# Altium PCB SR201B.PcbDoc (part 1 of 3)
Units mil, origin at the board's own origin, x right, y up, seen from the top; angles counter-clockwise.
Board outline 4100 x 3600 mil, 4 copper layers (Top Layer, Signal Layer 1, Signal Layer 2, Bottom Layer), stack 61.6 mil thick; 173 components, 61 nets, 385 pads, 260 vias.
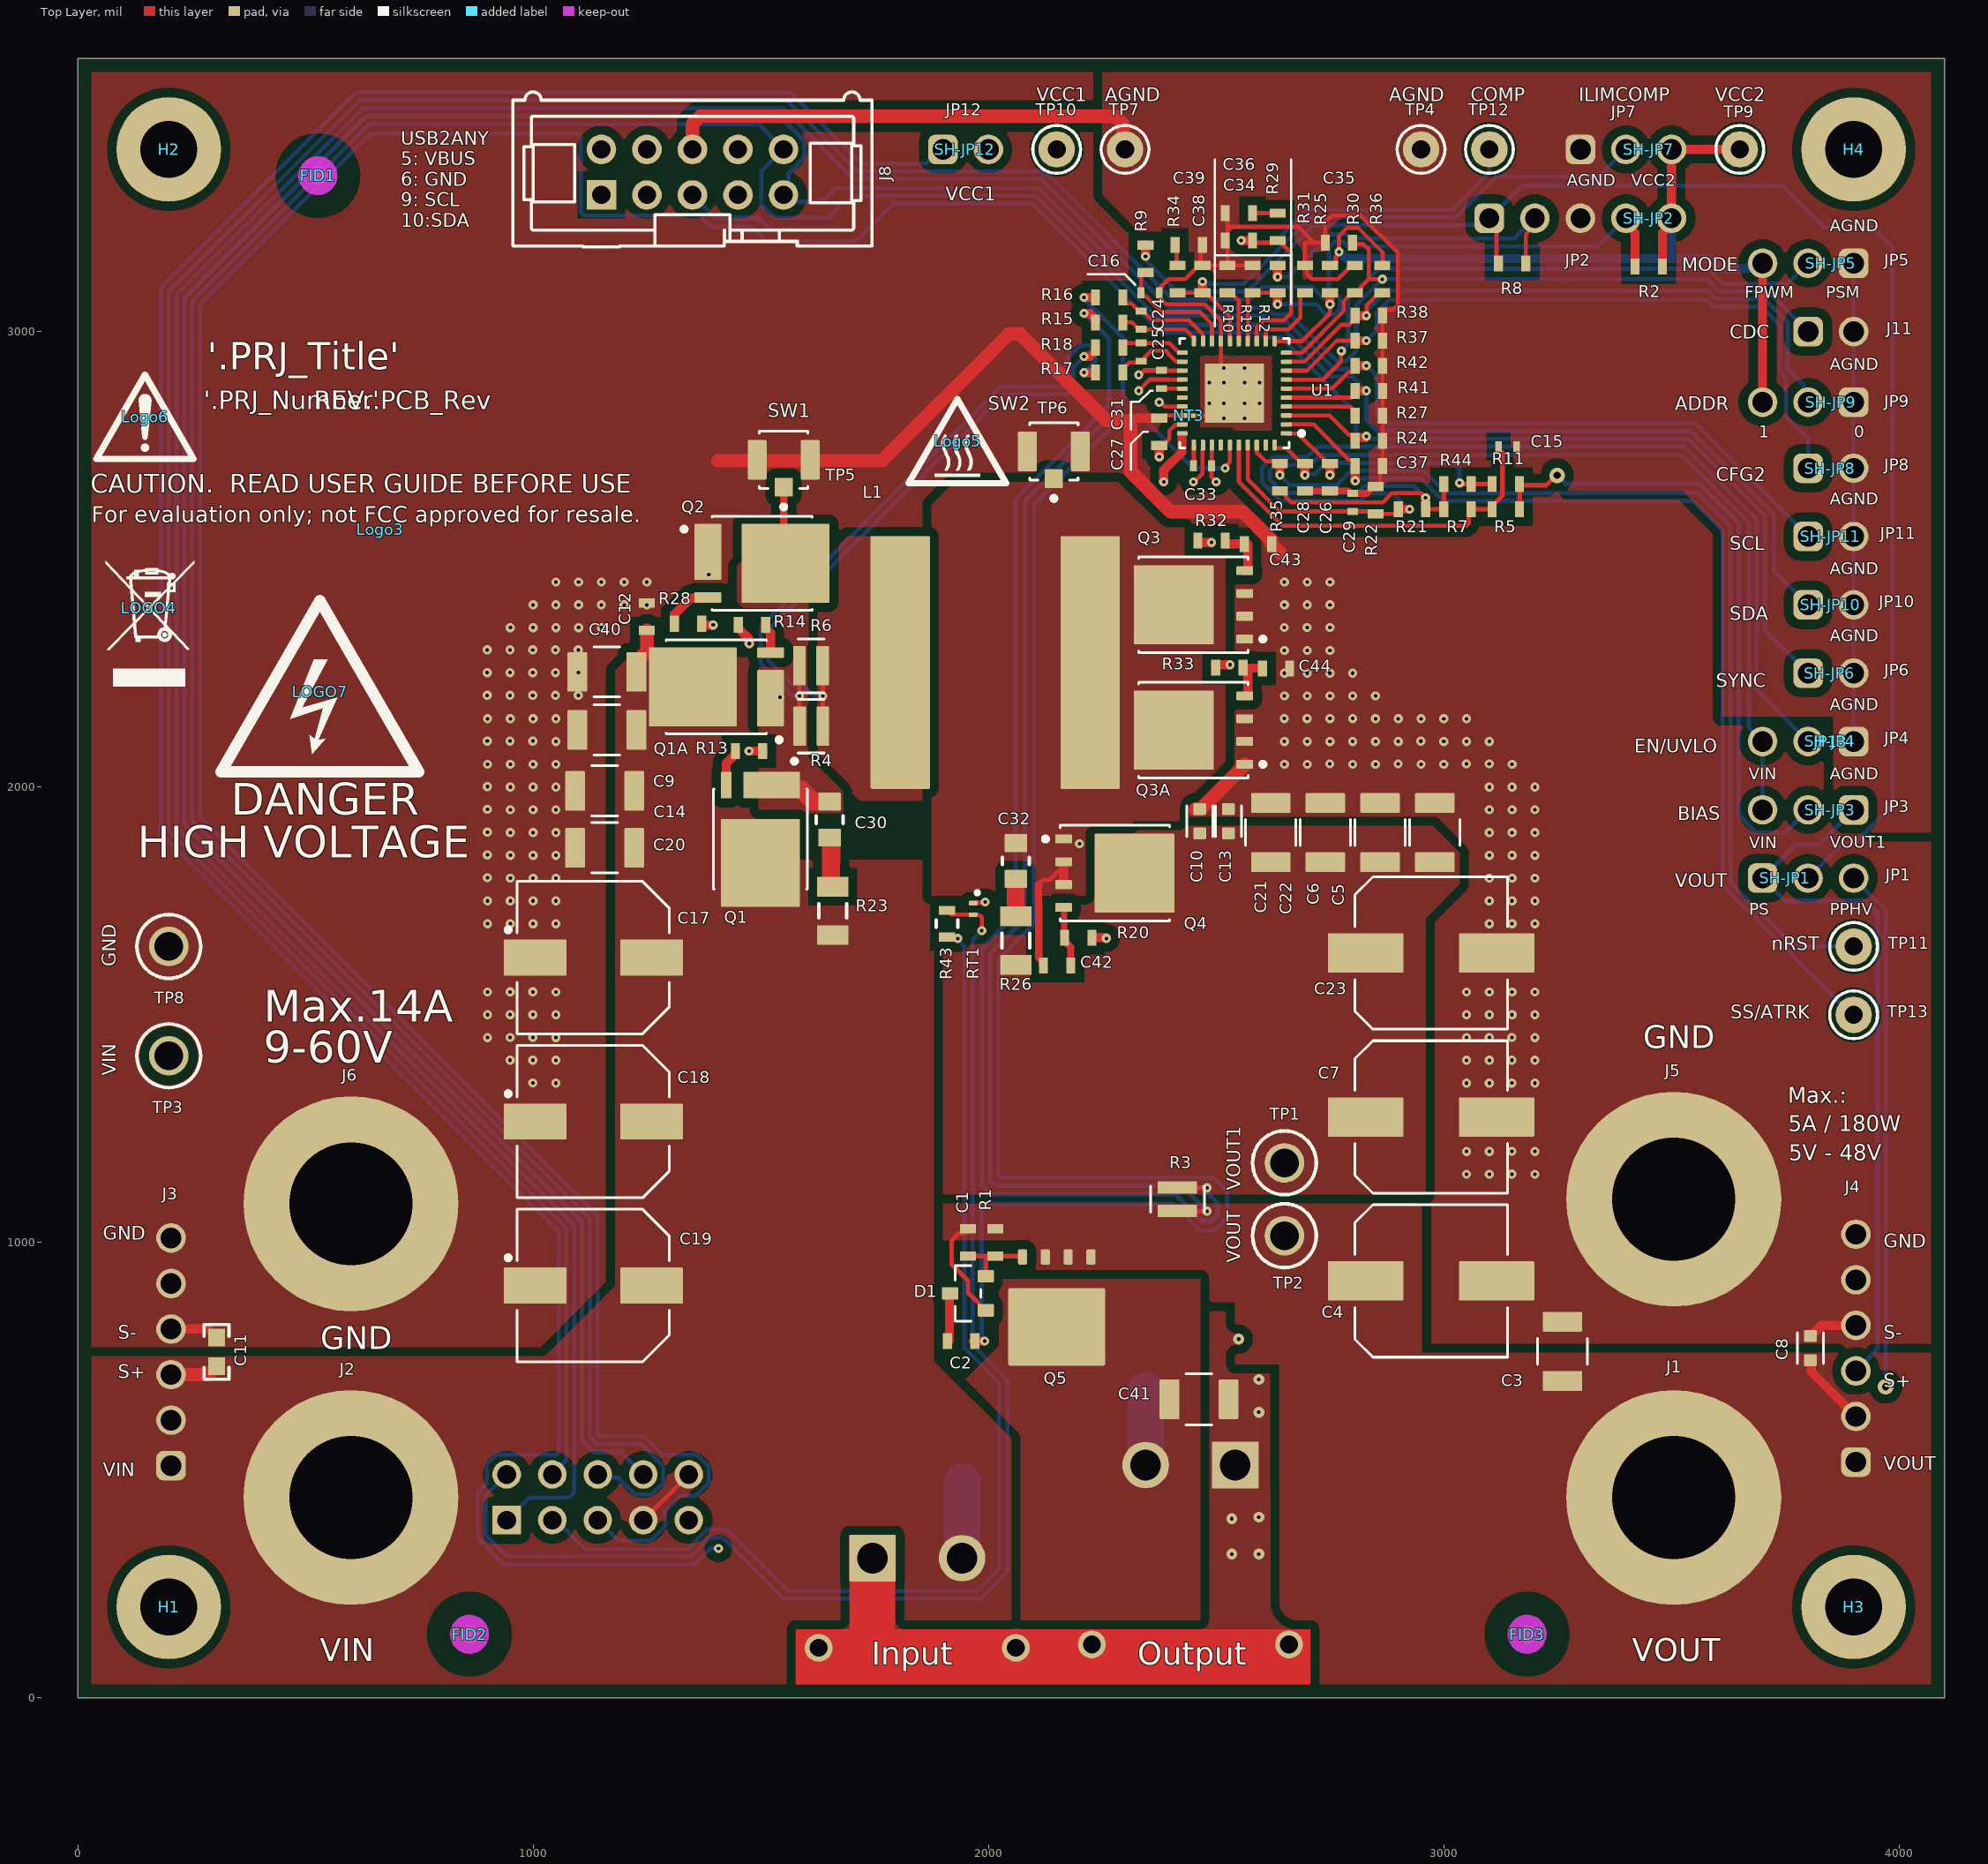
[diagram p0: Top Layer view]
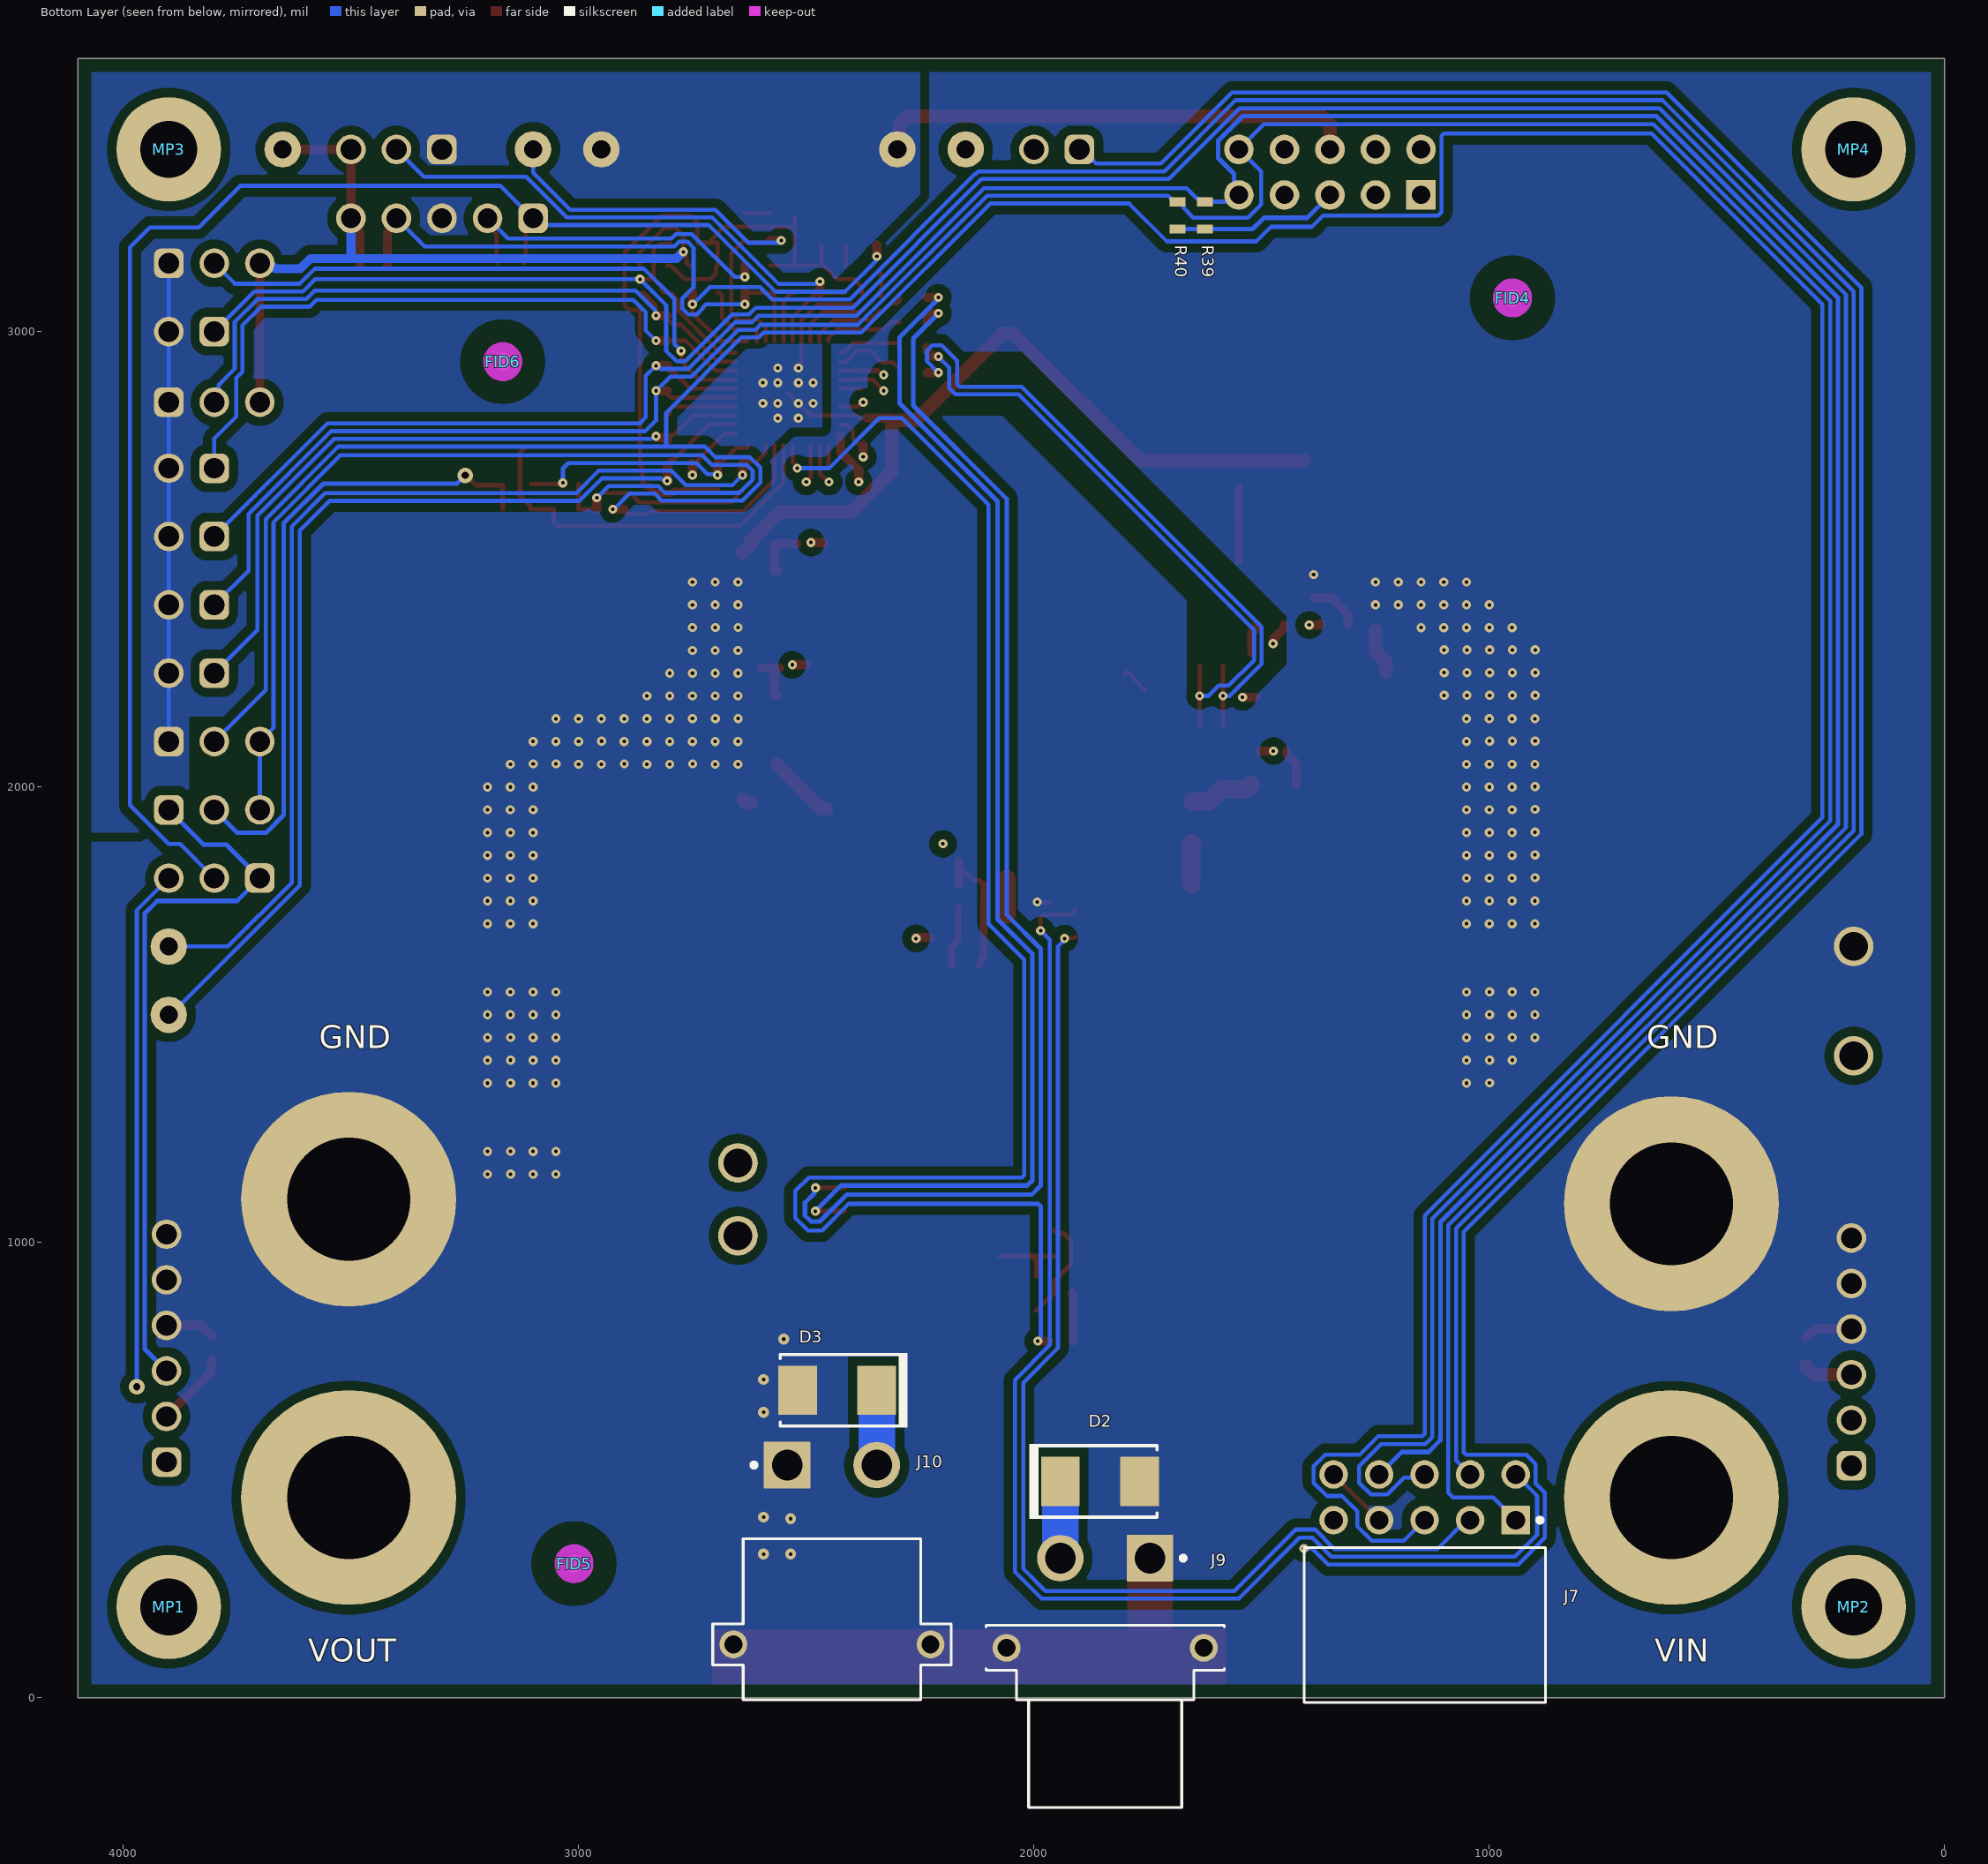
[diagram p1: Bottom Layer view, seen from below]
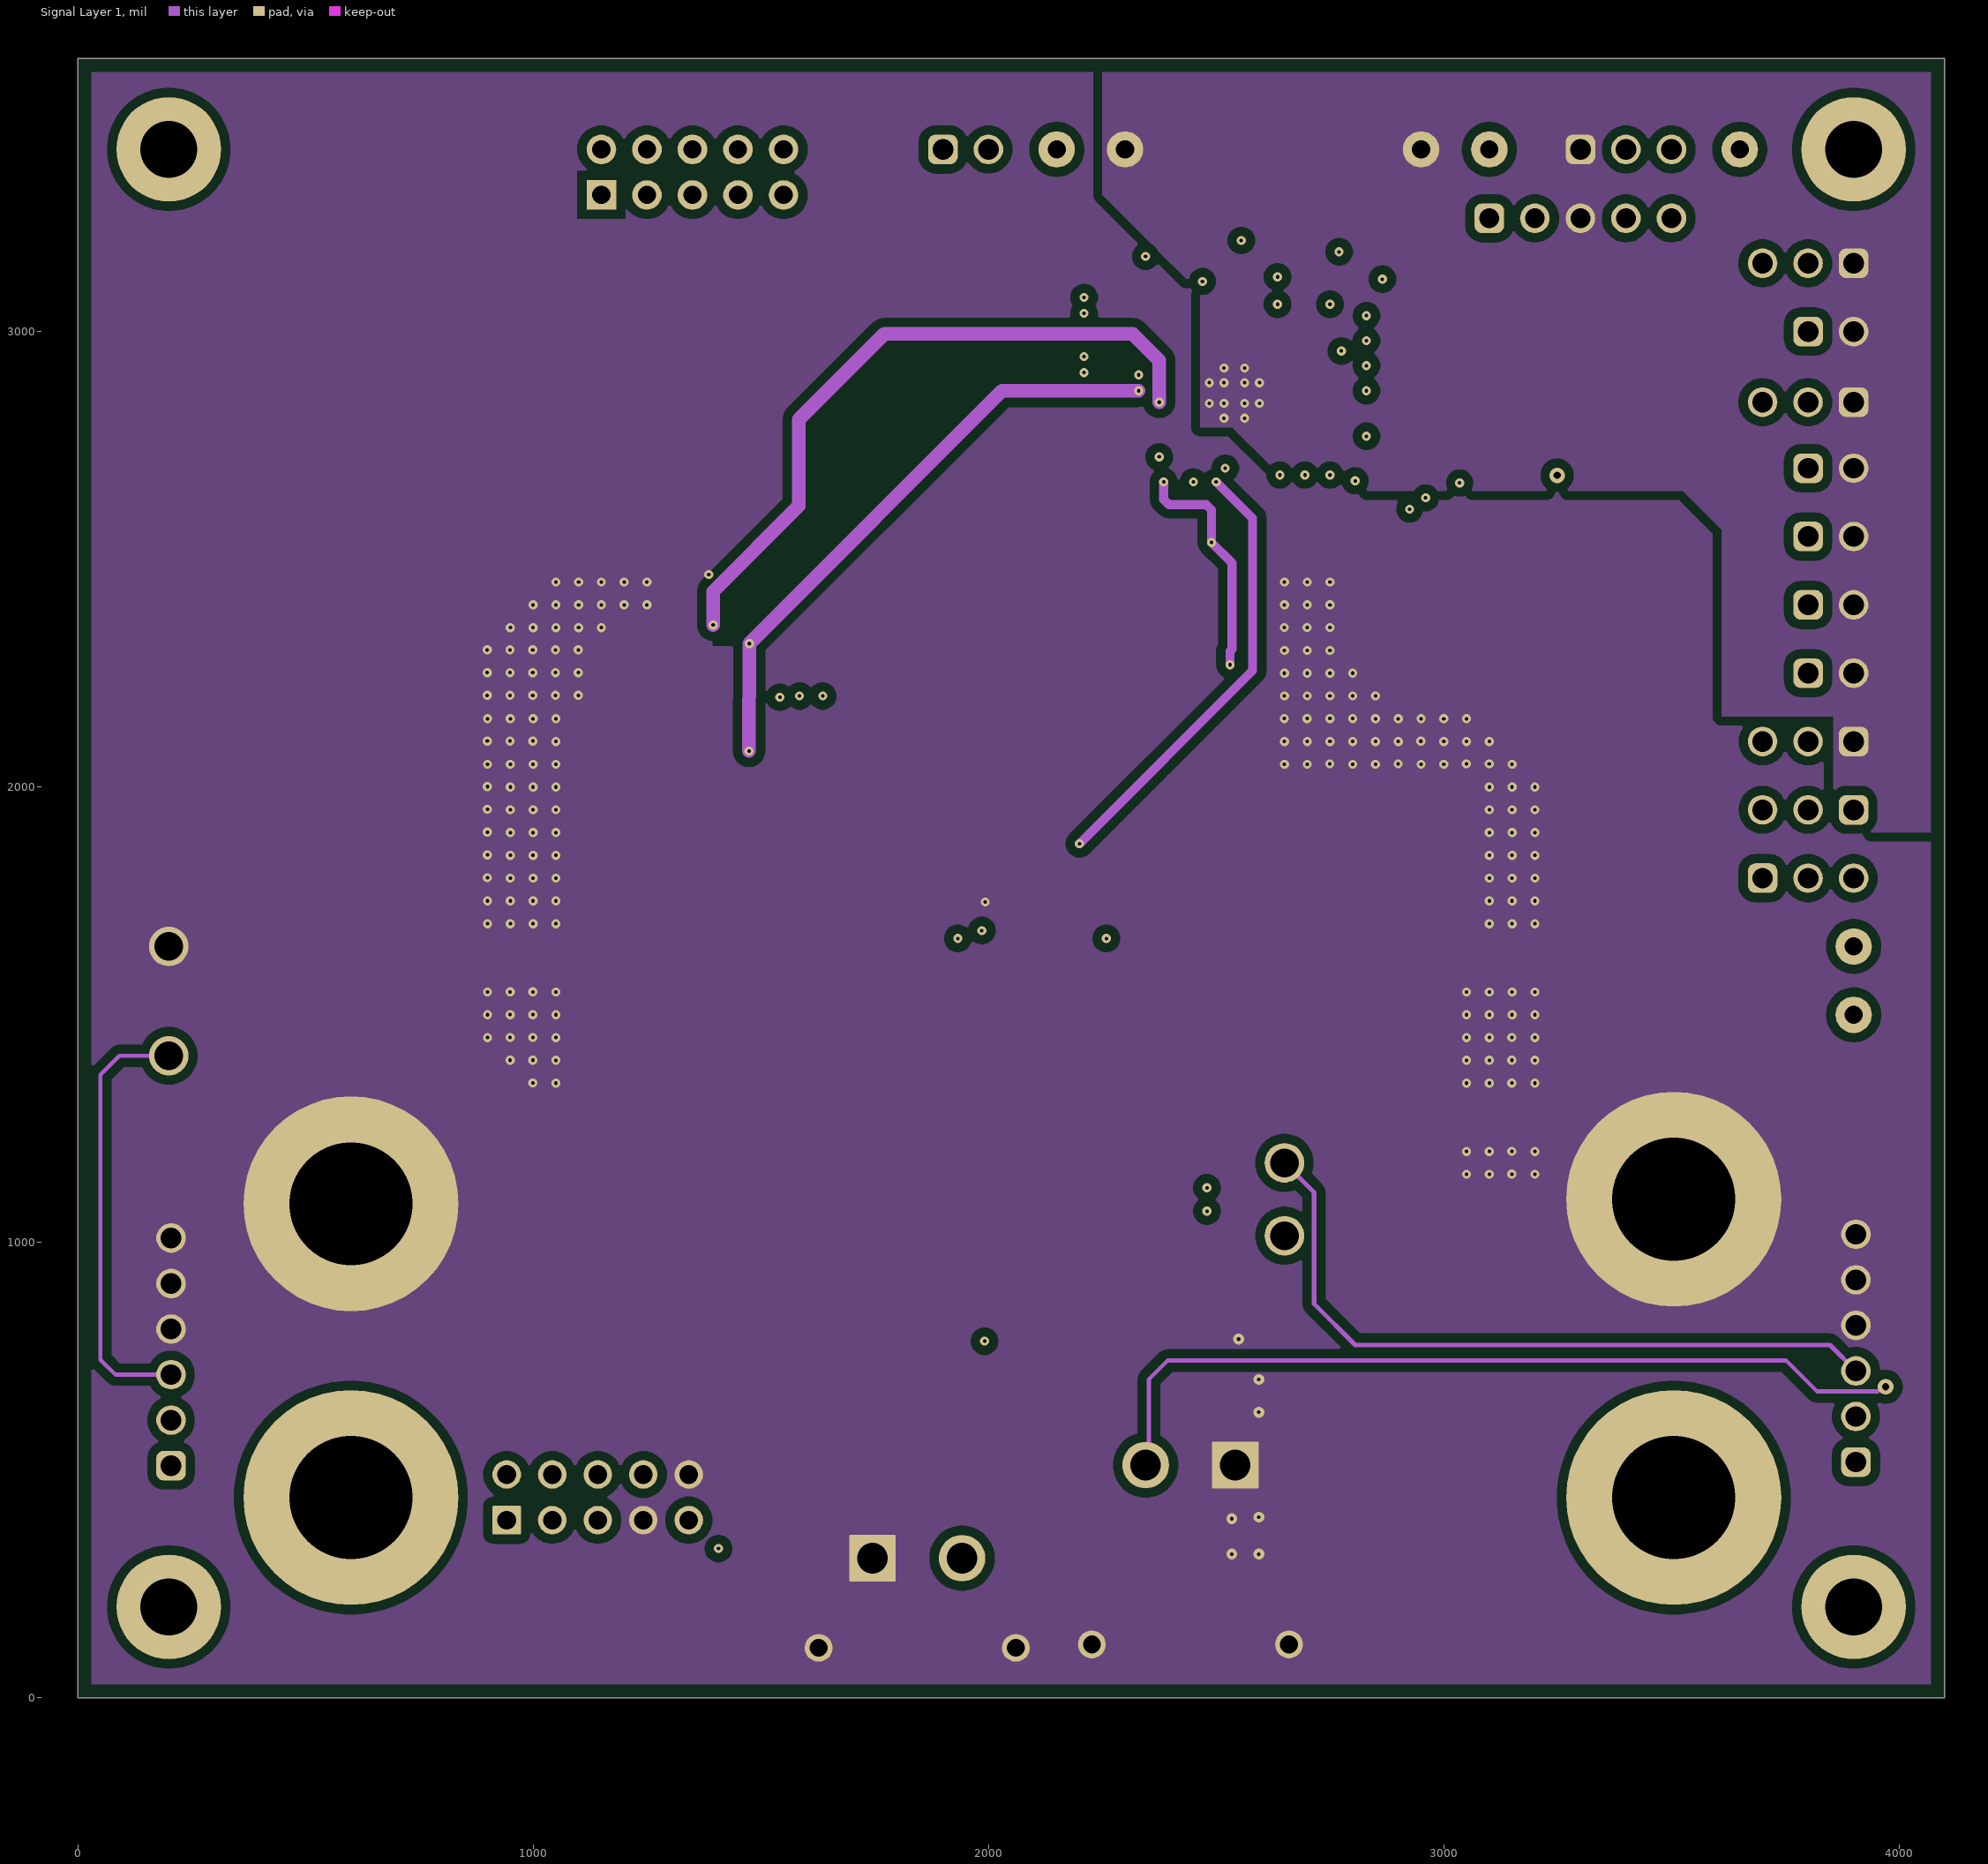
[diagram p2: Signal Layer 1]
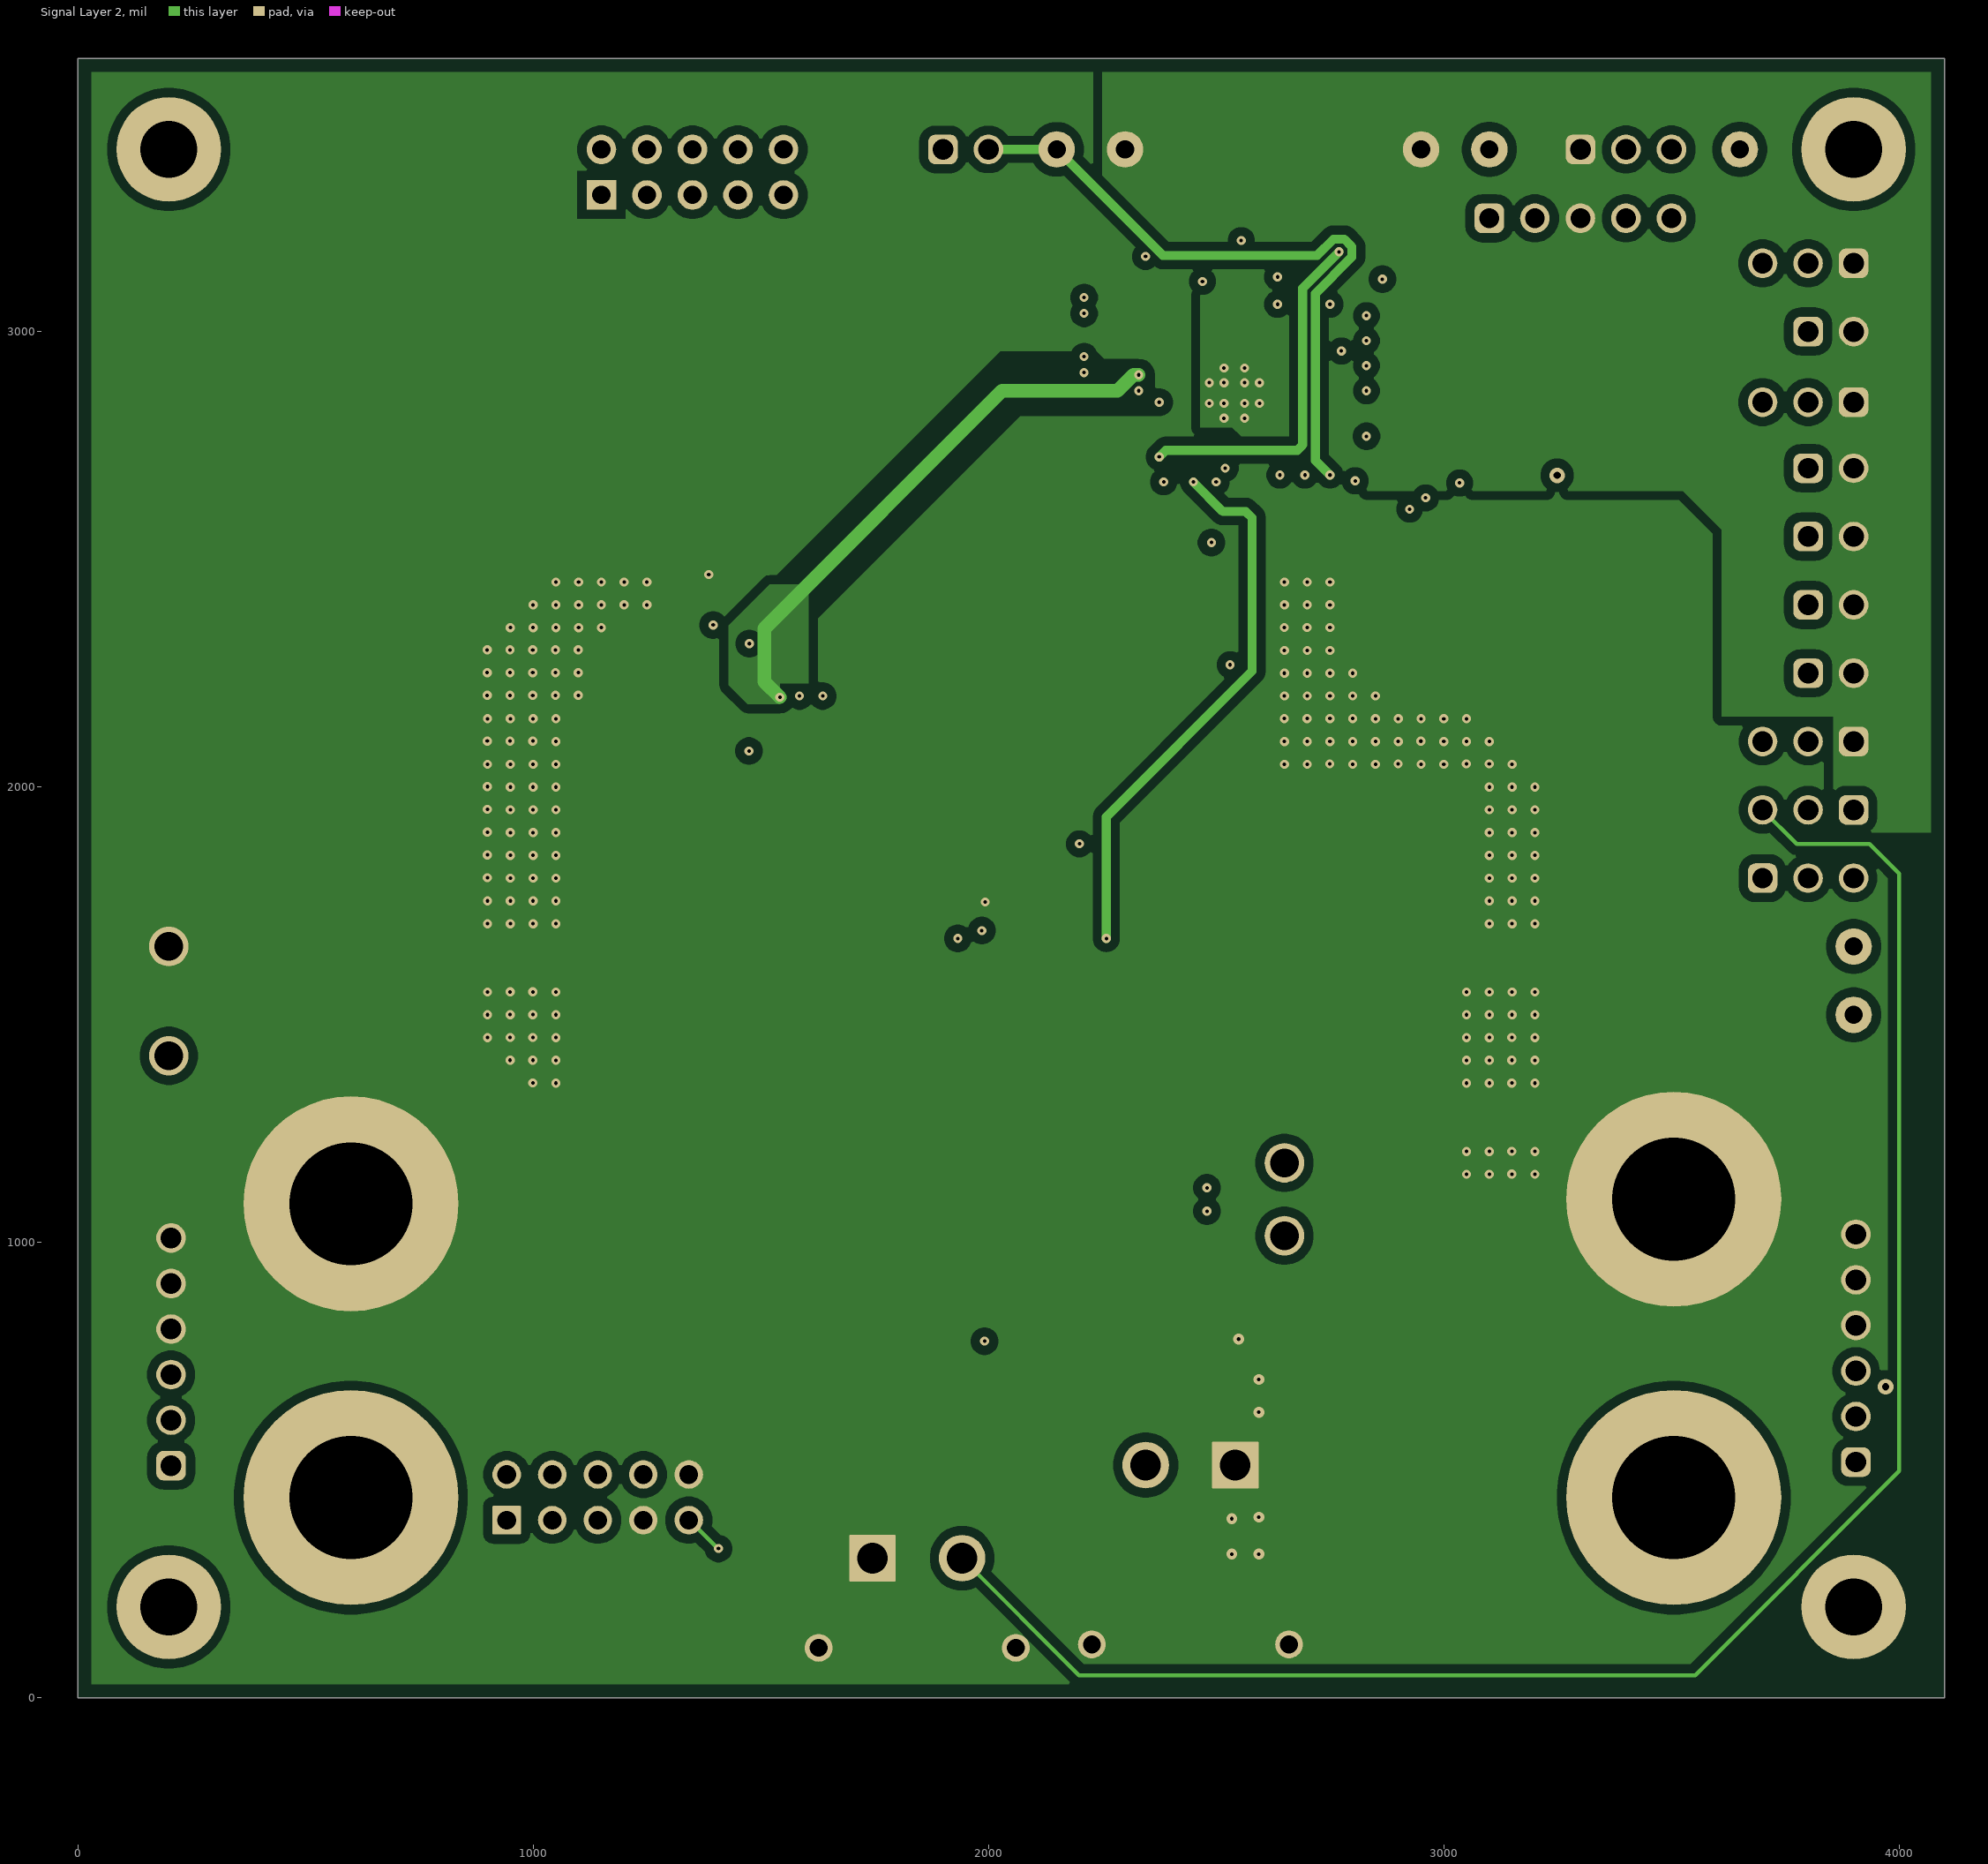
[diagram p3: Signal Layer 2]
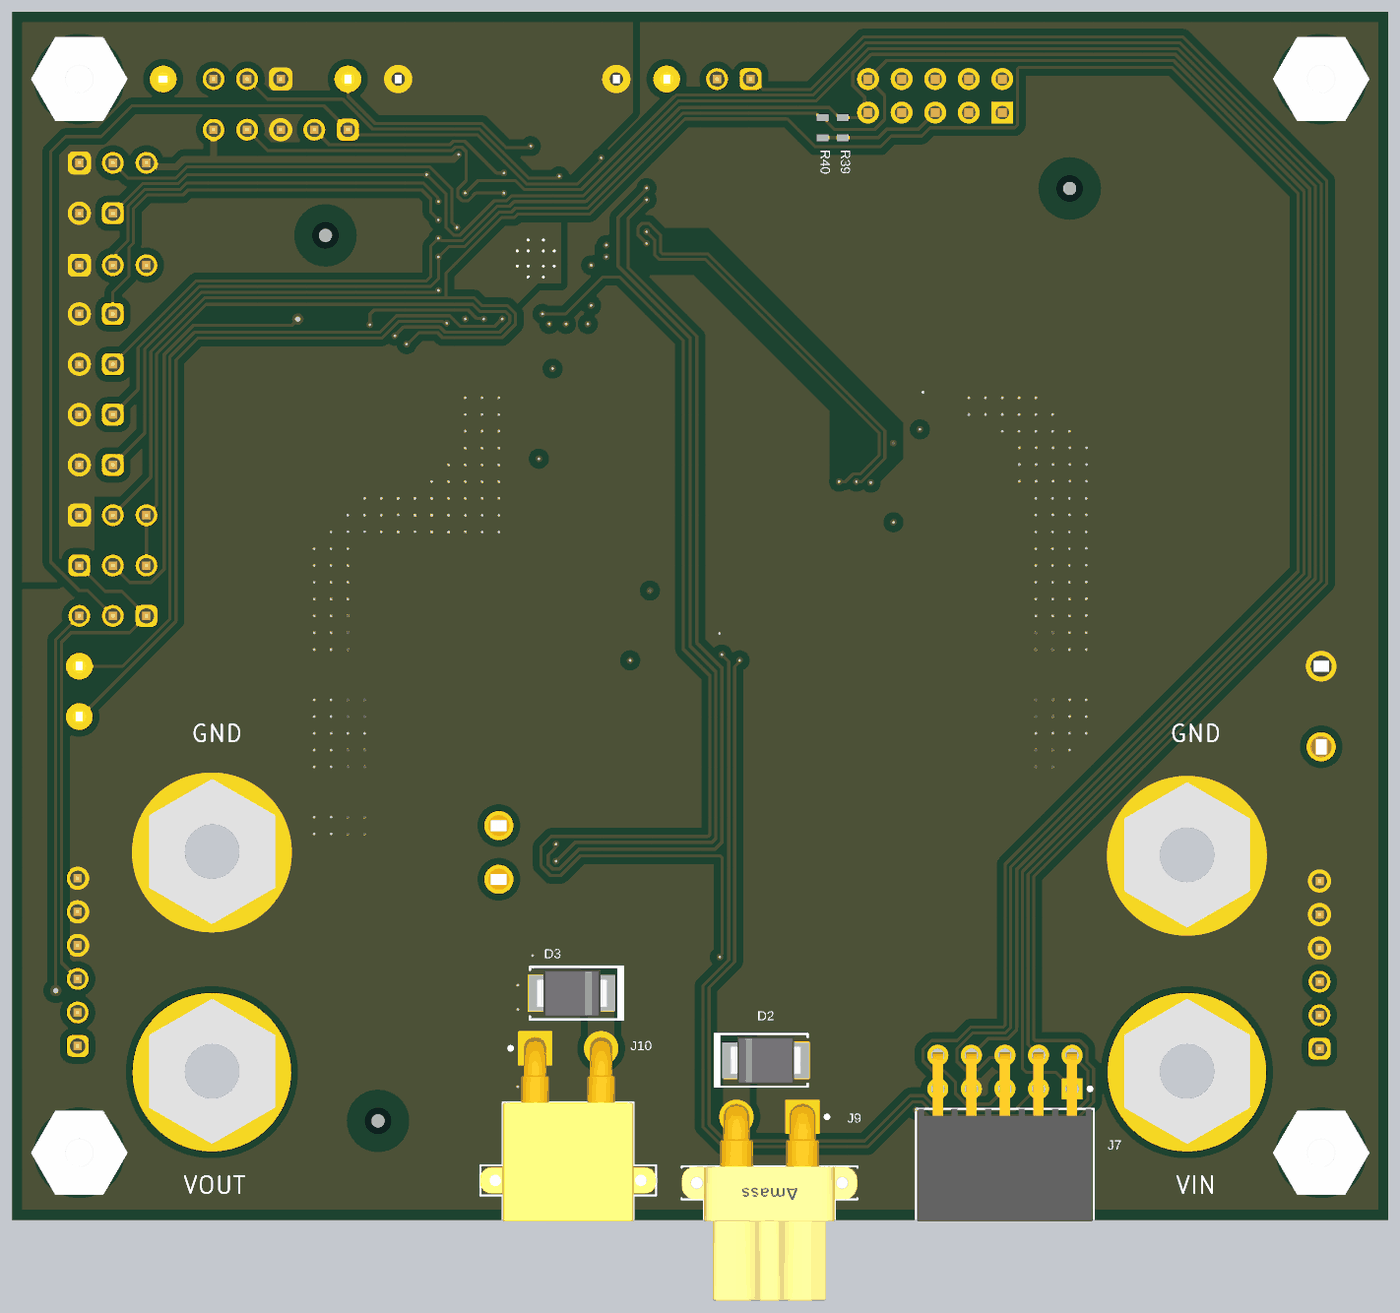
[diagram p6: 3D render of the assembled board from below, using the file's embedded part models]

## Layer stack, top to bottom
Top Solder: solder mask 0.4, Solder Resist, Dk 3.5
Top Layer: signal copper 2.8
Dielectric 1: prepreg 8, FR-4 High Tg, Dk 4.2
Signal Layer 1: signal copper 1.4
Dielectric 2: core 37.2, FR-4 High Tg, Dk 4.2
Signal Layer 2: signal copper 1.4
Dielectric 3: prepreg 8, FR-4 High Tg, Dk 4.2
Bottom Layer: signal copper 2.8
Bottom Solder: solder mask 0.4, Solder Resist, Dk 3.5

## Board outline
0,0 0,3600 4100,3600 4100,0

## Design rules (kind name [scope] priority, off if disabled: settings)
AcuteAngle [All] p1: minimum=4.50000000000000E+0001 checktracksonly=FALSE
AssemblyTestPointUsage [All] p1: valid=2
BoardOutlineClearance BoardOutlineClearance_MountingHoles [OnCopper and InComponentClass('Mounting Holes')] p1: gap=30 ignorepadtopadclearanceinfootprint=FALSE
BoardOutlineClearance BoardOutlineClearance_Poly [OnCopper and InPoly] p2: gap=25 ignorepadtopadclearanceinfootprint=FALSE
BoardOutlineClearance [OnCopper and Not InComponentClass('Logo') and not InComponentClass('FiducialMark') and not InRegion(1000,500,4000,800)] p3: gap=30 ignorepadtopadclearanceinfootprint=FALSE
Clearance Clearance_FiducialMark [IsKeepOut and InComponentClass('FiducialMark') vs IsPad and InComponentClass('FiducialMark')] p1: gap=0 ignorepadtopadclearanceinfootprint=FALSE
Clearance Clearance_Alt_Assembly [InComponent('JP4') or InComponent('JP13') vs InComponent('JP4') or InComponent('JP13')] p2: gap=7.87 ignorepadtopadclearanceinfootprint=FALSE except(0: Arc-Hole Track-Hole SMDPad-Hole THPad-THPad THPad-Hole Via-Hole Fill-Hole Poly-Hole Region-Hole Text-Hole)
Clearance Clearance_2 [InNetClass('HV') vs Not InNetClass('HV')] p3: gap=60 ignorepadtopadclearanceinfootprint=FALSE
Clearance Clearance_1 [InNetClass('MV') vs Not InNetClass('MV')] p4: gap=30 ignorepadtopadclearanceinfootprint=FALSE
Clearance Clearance_Keepouts [((IsTrack Or IsArc) And Not InPoly) And IsFree and IsKeepOut vs ((IsTrack Or IsArc) And Not InPoly) And IsFree and IsKeepOut] p5: gap=0 ignorepadtopadclearanceinfootprint=FALSE
Clearance Clearance_BoardEdge_MountingHoles [OnCopper and InComponentClass('Mounting Holes') vs IsKeepOut] p6: gap=40 ignorepadtopadclearanceinfootprint=FALSE except(0: Arc-Hole Track-Hole SMDPad-Hole THPad-Hole Via-Hole Fill-Hole Poly-Hole Region-Hole Text-Hole)
Clearance Clearance_BoardEdge_Poly [OnCopper and InPoly vs IsKeepOut] p7: gap=50 ignorepadtopadclearanceinfootprint=FALSE except(0: Arc-Hole Track-Hole SMDPad-Hole THPad-Hole Via-Hole Fill-Hole Poly-Hole Region-Hole Text-Hole)
Clearance Clearance_BoardEdge [OnCopper and Not InComponentClass('Logo') and not InComponentClass('FiducialMark') and not InRegion(1000,500,4000,800) and Not IsKeepout vs IsKeepOut] p8: gap=50 ignorepadtopadclearanceinfootprint=FALSE
Clearance Clearance_Poly [InPolygon] p9: gap=20 ignorepadtopadclearanceinfootprint=FALSE except(0: Arc-Hole Track-Hole SMDPad-Hole THPad-Hole Via-Hole Fill-Hole Poly-Hole Region-Hole Text-Hole)
Clearance [All] p10: gap=7.87 ignorepadtopadclearanceinfootprint=FALSE except(0: Arc-Hole Track-Hole SMDPad-Hole THPad-Hole Via-Hole Fill-Hole Poly-Hole Region-Hole Text-Hole)
ComponentClearance ComponentClearance_MP [All vs InComponent('MP1') or InComponent('MP2') or InComponent('MP3') or InComponent('MP4')] p1: gap=-1 collisioncheckmode=3 verticalgap=10 showdistances=FALSE
ComponentClearance ComponentClearance_Alt_Assembly [InComponent('JP4') vs InComponent('JP13')] p2: gap=-1 collisioncheckmode=3 verticalgap=0 showdistances=FALSE
ComponentClearance ComponentClearance_1 [InComponent('NT3')] p3: gap=-1 collisioncheckmode=3 verticalgap=0 showdistances=FALSE
ComponentClearance ComponentClearance_MountingHoles_FiducialMarks [InComponentClass('Mounting Holes') vs InComponentClass('FiducialMark')] p4: gap=50 collisioncheckmode=3 verticalgap=10 showdistances=FALSE
ComponentClearance ComponentClearance_Shunt [InComponentClass('Header') vs InComponentClass('Shunt') or InComponent('SH-JP1') or InComponent('SH-JP2') or InComponent('SH-JP3') or InComponent('SH-JP4') or InComponent('SH-JP5') or InComponent('SH-JP6') or InComponent('SH-JP7') or InComponent('SH-JP8') or InComponent('SH-JP9') or InComponent('SH-JP10') or InComponent('SH-JP11') or InComponent('SH-JP12')] p5: gap=-1 collisioncheckmode=3 verticalgap=0 showdistances=FALSE
ComponentClearance ComponentClearance_Logo [InComponentClass('Logo')] p6: gap=30 collisioncheckmode=3 verticalgap=10 showdistances=FALSE
ComponentClearance ComponentClearance_ScrewToNut [(HasFootprint('NY PMS 440 0025 PH')) vs (HasFootprint('Keystone_1902C'))] p7: gap=5 collisioncheckmode=3 verticalgap=100000 showdistances=FALSE
ComponentClearance ComponentClearance_MountingHoles [InComponentClass('Mounting Holes')] p8: gap=100 collisioncheckmode=3 verticalgap=10 showdistances=FALSE
ComponentClearance ComponentClearance_SmallPassives [HasFootprint('0201*') or HasFootprint('0402*') or HasFootprint('0508') or HasFootprint('0603*') or HasFootprint('0612') or HasFootprint('0805*') or HasFootprint('0815*') or HasFootprint('0830*') or HasFootprint('1206*') or HasFootprint('1210*') or HasFootprint('1808*') or HasFootprint('1812*') or HasFootprint('1825*') or HasFootprint('2010*') or HasFootprint('2220*') or HasFootprint('2225*') or HasFootprint('2512*') or HasFootprint('2728*') or HasFootprint('3518*') vs HasFootprint('0201*') or HasFootprint('0402*') or HasFootprint('0508') or HasFootprint('0603*') or HasFootprint('0612') or HasFootprint('0805*') or HasFootprint('0815*') or HasFootprint('0830*') or HasFootprint('1206*') or HasFootprint('1210*') or HasFootprint('1808*') or HasFootprint('1812*') or HasFootprint('1825*') or HasFootprint('2010*') or HasFootprint('2220*') or HasFootprint('2225*') or HasFootprint('2512*') or HasFootprint('2728*') or HasFootprint('3518*')] p9: gap=17.5 collisioncheckmode=3 verticalgap=17.5 showdistances=FALSE
ComponentClearance ComponentClearance_THtoSMT [IsThruComponent vs IsSMTComponent] p10: gap=20 collisioncheckmode=3 verticalgap=10 showdistances=FALSE
ComponentClearance ComponentClearance_THtoTH [IsThruComponent vs IsThruComponent] p11: gap=20 collisioncheckmode=3 verticalgap=20 showdistances=FALSE
ComponentClearance [All] p12: gap=10 collisioncheckmode=3 verticalgap=10 showdistances=FALSE
DiffPairsRouting [All] p1: maxlimit=100 minlimit=10 mostfreqgap=10 toplayer_minwidth=15 toplayer_maxwidth=15 toplayer_prefwidth=15 midlayer1_minwidth=15 midlayer1_maxwidth=15 midlayer1_prefwidth=15 midlayer2_minwidth=15 midlayer2_maxwidth=15 midlayer2_prefwidth=15 bottomlayer_minwidth=15 bottomlayer_maxwidth=15 bottomlayer_prefwidth=15 maxuncoupledlength=1000
FabricationTestPointUsage TestPointUsage [All] p1: valid=2 allowmultiple=FALSE
FabricationTestpoint Testpoint [All] p1: side=3 testpointundercomponent=TRUE minsize=40 maxsize=100 preferedsize=60 minholesize=0 maxholesize=40 preferedholesize=32 testpointgrid=1 allowsidetop=TRUE allowsidebottom=TRUE usegrid=TRUE gridtolerance=0.01
FanoutControl Fanout_LCC [IsLCC] p1: bgadir=Out bgaviamode=Centered fanoutstyle=Auto fanoutdirection=Alternating viagrid=1 // Fanout_LCC (Default Rule)
FanoutControl Fanout_BGA [IsBGA] p2: bgadir=Out bgaviamode=Centered fanoutstyle=Auto fanoutdirection=Alternating viagrid=1 // Fanout_BGA (Default Rule)
FanoutControl Fanout_Default [All] p4: bgadir=Out bgaviamode=Centered fanoutstyle=Auto fanoutdirection=Alternating viagrid=1 // Fanout_Default (Default Rule)
FanoutControl Fanout_Small [(CompPinCount < 5)] p5: bgadir=Out bgaviamode=Centered fanoutstyle=Auto fanoutdirection=OutThenIn viagrid=1 // Fanout_Small (Default Rule)
Height [All] p1: minheight=0 maxheight=3000 prefheight=500
HoleSize [All] p1: absolutevalues=TRUE maxlimit=271 minlimit=7.87 maxpercent=80.000 minpercent=20.000
HoleToHoleClearance HoileToHole_Alt_Assembly [InComponent('JP4') OR InComponent('JP13') vs InComponent('JP4') OR InComponent('JP13')] p1: gap=0 allowstackedmicrovias=FALSE
HoleToHoleClearance [All] p2: gap=10 allowstackedmicrovias=TRUE
MinimumAnnularRing MinimumAnnularRing_ThermalPadVias [IsVia and InAnyComponent] p1: minimumring=5.91
MinimumAnnularRing [All] p2: minimumring=6
MinimumSolderMaskSliver MinimumSolderMaskSliver_Logo [InComponentClass('Logo') vs InComponentClass('Logo')] p1: minsoldermaskwidth=0.7
MinimumSolderMaskSliver [All] p2: minsoldermaskwidth=3.94
PlaneConnect [All] p1: planeconnectstyle=Direct reliefexpansion=10 reliefentries=4 reliefconductorwidth=10 reliefairgap=10
PolygonConnect PolygonConnect_15 [All vs IsNamedPolygon('C109_2') Or  IsNamedPolygon('C107_2') Or  IsNamedPolygon('HV') Or  IsNamedPolygon('Q203_5') Or  IsNamedPolygon('C107_2') Or  IsNamedPolygon('HS') Or  IsNamedPolygon('Q201_5') Or  IsNamedPolygon('Q203_5') Or  IsNamedPolygon('C106_2') Or  IsNamedPolygon('C108_2') Or  IsNamedPolygon('Vout') Or  IsNamedPolygon('Q203_5') Or  IsNamedPolygon('C108_2') Or  IsNamedPolygon('C113_2') Or  IsNamedPolygon('Q203_5') Or  IsNamedPolygon('Q201_5') Or  IsNamedPolygon('C107_2') Or  IsNamedPolygon('C102_1') Or  IsNamedPolygon('SGND') Or  IsNamedPolygon('GND') Or  IsNamedPolygon('SGND') Or  IsNamedPolygon('GND') Or  IsNamedPolygon('IN+') Or  IsNamedPolygon('IN+') Or  IsNamedPolygon('Q201_5') Or  IsNamedPolygon('Q201_5') Or  IsNamedPolygon('SGND') Or  IsNamedPolygon('SGND') Or  IsNamedPolygon('Vout') Or  IsNamedPolygon('Vout') Or  IsNamedPolygon('IN+') Or  IsNamedPolygon('GND') Or  IsNamedPolygon('IN+') Or  IsNamedPolygon('GND')] p1: connectstyle=Direct reliefconductorwidth=10 reliefentries=4 polygonreliefangle="90 Angle" airgapwidth=10
PolygonConnect PolygonConnect_14 [All vs IsNamedPolygon('C106_2') Or  IsNamedPolygon('C107_2') Or  IsNamedPolygon('C107_2') Or  IsNamedPolygon('C107_2') Or  IsNamedPolygon('C102_1') Or  IsNamedPolygon('Q203_5') Or  IsNamedPolygon('Vout') Or  IsNamedPolygon('Q203_5') Or  IsNamedPolygon('Q203_5') Or  IsNamedPolygon('Q201_5') Or  IsNamedPolygon('C108_2') Or  IsNamedPolygon('Q203_5') Or  IsNamedPolygon('HS') Or  IsNamedPolygon('HV') Or  IsNamedPolygon('C108_2') Or  IsNamedPolygon('Q201_5') Or  IsNamedPolygon('C109_2') Or  IsNamedPolygon('Q201_5') Or  IsNamedPolygon('Q201_5') Or  IsNamedPolygon('C113_2')] p2: connectstyle=Direct reliefconductorwidth=10 reliefentries=4 polygonreliefangle="90 Angle" airgapwidth=10
PolygonConnect PolygonConnect_13 [All vs IsNamedPolygon('C102_1') Or  IsNamedPolygon('HV') Or  IsNamedPolygon('C107_2') Or  IsNamedPolygon('C109_2') Or  IsNamedPolygon('C107_2') Or  IsNamedPolygon('C108_2') Or  IsNamedPolygon('C106_2') Or  IsNamedPolygon('C108_2') Or  IsNamedPolygon('C113_2') Or  IsNamedPolygon('C107_2')] p3: connectstyle=Direct reliefconductorwidth=10 reliefentries=4 polygonreliefangle="90 Angle" airgapwidth=10
PolygonConnect PolygonConnect_12 [All vs IsNamedPolygon('C107_2') Or  IsNamedPolygon('C113_2') Or  IsNamedPolygon('C106_2') Or  IsNamedPolygon('C107_2') Or  IsNamedPolygon('C107_2') Or  IsNamedPolygon('C102_1')] p4: connectstyle=Direct reliefconductorwidth=10 reliefentries=4 polygonreliefangle="90 Angle" airgapwidth=10
PolygonConnect PolygonConnect_11 [All vs IsNamedPolygon('C106_2') Or  IsNamedPolygon('C102_1') Or  IsNamedPolygon('C107_2') Or  IsNamedPolygon('C107_2') Or  IsNamedPolygon('C107_2')] p5: connectstyle=Direct reliefconductorwidth=10 reliefentries=4 polygonreliefangle="90 Angle" airgapwidth=10
PolygonConnect PolygonConnect_10 [All vs IsNamedPolygon('C106_2')] p6: connectstyle=Direct reliefconductorwidth=10 reliefentries=4 polygonreliefangle="90 Angle" airgapwidth=10
PolygonConnect PolygonConnect_9 [All vs IsNamedPolygon('C11_1') Or  IsNamedPolygon('Vin') Or  IsNamedPolygon('Vin') Or  IsNamedPolygon('5V') Or  IsNamedPolygon('D6_2') Or  IsNamedPolygon('Q3_3') Or  IsNamedPolygon('GND2') Or  IsNamedPolygon('GND2') Or  IsNamedPolygon('GND') Or  IsNamedPolygon('Q3_4') Or  IsNamedPolygon('12V5') Or  IsNamedPolygon('GND') Or  IsNamedPolygon('12V5') Or  IsNamedPolygon('D3_1')] p7: connectstyle=Direct reliefconductorwidth=10 reliefentries=4 polygonreliefangle="90 Angle" airgapwidth=10
PolygonConnect PolygonConnect_8 [All vs IsNamedPolygon('C11_1') Or  IsNamedPolygon('Vin') Or  IsNamedPolygon('12V5') Or  IsNamedPolygon('Q3_3') Or  IsNamedPolygon('GND2') Or  IsNamedPolygon('GND2') Or  IsNamedPolygon('5V') Or  IsNamedPolygon('Q3_4') Or  IsNamedPolygon('12V5')] p8: connectstyle=Direct reliefconductorwidth=10 reliefentries=4 polygonreliefangle="90 Angle" airgapwidth=10
PolygonConnect PolygonConnect_7 [All vs IsNamedPolygon('GND2') Or  IsNamedPolygon('GND2') Or  IsNamedPolygon('5V') Or  IsNamedPolygon('12V5') Or  IsNamedPolygon('12V5') Or  IsNamedPolygon('C11_1')] p9: connectstyle=Direct reliefconductorwidth=10 reliefentries=4 polygonreliefangle="90 Angle" airgapwidth=10
PolygonConnect PolygonConnect_6 [All vs IsNamedPolygon('GND2') Or  IsNamedPolygon('SGND') Or  IsNamedPolygon('GND1') Or  IsNamedPolygon('C901_1') Or  IsNamedPolygon('SGND') Or  IsNamedPolygon('GND2') Or  IsNamedPolygon('GND1')] p10: connectstyle=Direct reliefconductorwidth=10 reliefentries=4 polygonreliefangle="90 Angle" airgapwidth=10
PolygonConnect PolygonConnect_5 [All vs IsNamedPolygon('GND1') Or  IsNamedPolygon('GND1')] p11: connectstyle=Direct reliefconductorwidth=10 reliefentries=4 polygonreliefangle="90 Angle" airgapwidth=10
PolygonConnect PolygonConnect_4 [All vs IsNamedPolygon('C21_1') Or  IsNamedPolygon('C5_1') Or  IsNamedPolygon('C12_2') Or  IsNamedPolygon('C2_2') Or  IsNamedPolygon('C13_1') Or  IsNamedPolygon('C28_1') Or  IsNamedPolygon('C6_1') Or  IsNamedPolygon('GND') Or  IsNamedPolygon('GND2') Or  IsNamedPolygon('C14_1') Or  IsNamedPolygon('C13_1') Or  IsNamedPolygon('Q1_3') Or  IsNamedPolygon('C14_1') Or  IsNamedPolygon('C5_1') Or  IsNamedPolygon('GND2') Or  IsNamedPolygon('C28_1') Or  IsNamedPolygon('D5_2') Or  IsNamedPolygon('D6_2') Or  IsNamedPolygon('D2_1') Or  IsNamedPolygon('C12_2') Or  IsNamedPolygon('D2_1') Or  IsNamedPolygon('C4_1') Or  IsNamedPolygon('C4_1') Or  IsNamedPolygon('C2_2') Or  IsNamedPolygon('GND') Or  IsNamedPolygon('C33_1') Or  IsNamedPolygon('C9_1')] p12: connectstyle=Direct reliefconductorwidth=10 reliefentries=4 polygonreliefangle="90 Angle" airgapwidth=10
PolygonConnect PolygonConnect_3 [All vs IsNamedPolygon('C28_1') Or  IsNamedPolygon('C12_2') Or  IsNamedPolygon('C28_1') Or  IsNamedPolygon('C9_1') Or  IsNamedPolygon('D5_2') Or  IsNamedPolygon('C12_2') Or  IsNamedPolygon('C2_2') Or  IsNamedPolygon('C14_1') Or  IsNamedPolygon('C4_1') Or  IsNamedPolygon('C14_1') Or  IsNamedPolygon('D6_2') Or  IsNamedPolygon('GND2') Or  IsNamedPolygon('Q1_3') Or  IsNamedPolygon('C5_1') Or  IsNamedPolygon('D2_1') Or  IsNamedPolygon('C4_1') Or  IsNamedPolygon('C13_1') Or  IsNamedPolygon('C5_1') Or  IsNamedPolygon('C13_1') Or  IsNamedPolygon('C33_1') Or  IsNamedPolygon('D2_1') Or  IsNamedPolygon('GND') Or  IsNamedPolygon('GND') Or  IsNamedPolygon('GND2') Or  IsNamedPolygon('C2_2') Or  IsNamedPolygon('C6_1') Or  IsNamedPolygon('C21_1')] p13: connectstyle=Direct reliefconductorwidth=10 reliefentries=4 polygonreliefangle="90 Angle" airgapwidth=10
PolygonConnect PolygonConnect_2 [All vs IsNamedPolygon('C21_1') Or  IsNamedPolygon('C4_1') Or  IsNamedPolygon('D5_2') Or  IsNamedPolygon('C5_1') Or  IsNamedPolygon('C14_1') Or  IsNamedPolygon('C13_1') Or  IsNamedPolygon('C4_1') Or  IsNamedPolygon('C33_1') Or  IsNamedPolygon('C12_2') Or  IsNamedPolygon('D2_1') Or  IsNamedPolygon('C2_2') Or  IsNamedPolygon('C28_1') Or  IsNamedPolygon('C12_2') Or  IsNamedPolygon('D2_1') Or  IsNamedPolygon('C5_1') Or  IsNamedPolygon('Q1_3') Or  IsNamedPolygon('GND') Or  IsNamedPolygon('D6_2') Or  IsNamedPolygon('C6_1') Or  IsNamedPolygon('C2_2') Or  IsNamedPolygon('C14_1') Or  IsNamedPolygon('C28_1') Or  IsNamedPolygon('C13_1') Or  IsNamedPolygon('C9_1') Or  IsNamedPolygon('GND')] p14: connectstyle=Direct reliefconductorwidth=10 reliefentries=4 polygonreliefangle="90 Angle" airgapwidth=10
PolygonConnect PolygonConnect_1 [All vs IsNamedPolygon('C28_1') Or  IsNamedPolygon('D5_2') Or  IsNamedPolygon('C5_1') Or  IsNamedPolygon('C5_1') Or  IsNamedPolygon('D2_1') Or  IsNamedPolygon('C21_1') Or  IsNamedPolygon('C9_1') Or  IsNamedPolygon('C4_1') Or  IsNamedPolygon('C14_1') Or  IsNamedPolygon('C28_1') Or  IsNamedPolygon('C6_1') Or  IsNamedPolygon('C12_2') Or  IsNamedPolygon('C33_1') Or  IsNamedPolygon('C4_1') Or  IsNamedPolygon('C13_1') Or  IsNamedPolygon('C12_2') Or  IsNamedPolygon('D6_2') Or  IsNamedPolygon('C2_2') Or  IsNamedPolygon('C14_1') Or  IsNamedPolygon('D2_1') Or  IsNamedPolygon('C2_2') Or  IsNamedPolygon('C13_1')] p15: connectstyle=Direct reliefconductorwidth=10 reliefentries=4 polygonreliefangle="90 Angle" airgapwidth=10
PolygonConnect [All] p16: connectstyle=Direct reliefconductorwidth=10 reliefentries=4 polygonreliefangle="90 Angle" airgapwidth=10
RoutingVias ThermalPadVias [IsVia and InAnyComponent] p1: holewidth=7.87 width=19.68 viastyle="Through Hole" minholewidth=7.87 minwidth=19.68 maxholewidth=12.99 maxwidth=23.62
RoutingVias [All] p2: holewidth=16 width=34 viastyle="Through Hole" minholewidth=7.87 minwidth=20 maxholewidth=40 maxwidth=65
SilkToBoardRegionClearance [Not ((IsComment or IsDesignator) And (Hide <> 'False')) and not InRegion(1000,500,4000,800)] p1:
SilkToSilkClearance SilkToSilkClearance_Pb-FreeLogo [(HasFootprint('Pb-Free_Overlay_Medium') OR HasFootprint('Pb-Free_Overlay_Small')) vs (HasFootprint('Pb-Free_Overlay_Medium') OR HasFootprint('Pb-Free_Overlay_Small'))] p1: silktosilkclearance=0
SilkToSilkClearance [All] p2: silktosilkclearance=4
SilkToSolderMaskClearance SilkToComponentPadClearance [IsPad and InAnycomponent] p1: minsilkscreentomaskgap=5 clearancetoexposedcopper=TRUE
SilkToSolderMaskClearance "Silk to Solder Mask Opening" [All] p2: minsilkscreentomaskgap=4 clearancetoexposedcopper=FALSE
SolderMaskExpansion [All] p1: expansion=1.97 istentingtop=FALSE
SupplyNets "Schematic Supply Nets_2" [InNet('AGND')] p1: voltage=0.000
SupplyNets "Schematic Supply Nets_1" [InNet('GND')] p2: voltage=0.000
SupplyNets "Schematic Supply Nets" [InNet('VBUS')] p3: voltage=0.000
Width [All] p1: maxlimit=100 minlimit=6 preferedwidth=10 checkconnectedcopper=TRUE
13 further rules are at their usual default settings.

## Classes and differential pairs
component class SR201B_Hardware: !PCB FID1 FID2 FID3 FID4 FID5 FID6 H1 H2 H3 H4 Logo3 Logo4 Logo5 Logo6 LOGO7 MP1 MP2 MP3 MP4 SH-JP1 SH-JP2 SH-JP3 SH-JP4 SH-JP5 SH-JP6 SH-JP7 SH-JP8 SH-JP9 SH-JP10 SH-JP11 SH-JP12 ZZ2 ZZ3 ZZ4
component class FiducialMark: FID1 FID2 FID3 FID4 FID5 FID6
component class AssemblyNote: ZZ2 ZZ3 ZZ4
component class Header: J3 J4 J11 JP1 JP2 JP3 JP4 JP5 JP6 JP7 JP8 JP9 JP10 JP11 JP12 JP13

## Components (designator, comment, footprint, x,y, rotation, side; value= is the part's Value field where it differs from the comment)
C1 "CGA3E3X7S2A104K080AB" 0603S 1955,1000 r90 top value=0.1uF
C2 "CGA3E3X7S2A104K080AB" 0603S 1940,783.46 r180 top value=0.1uF
C3 "CGA6P1X7R2A106K250AC" FP-CGA6P1X7R2A106K250AC_1210-MFG 3260.59,761.15 r270 top value=10µF
C4 "A768KE276M1JLAE054" FP-A768KE276M1JLAE054_SMT_CAP_8MM3_8MM3-0 2972.24,915.59 r180 top value=27µF
C5 "CGA6P1X7R2A106K250AC" FP-CGA6P1X7R2A106K250AC_1210-MFG 2980,1900 r270 top value=10µF
C6 "CGA6P1X7R2A106K250AC" FP-CGA6P1X7R2A106K250AC_1210-MFG 2860,1900 r270 top value=10µF
C7 "A768KE276M1JLAE054" FP-A768KE276M1JLAE054_SMT_CAP_8MM3_8MM3-0 2972.24,1275.59 r180 top value=27µF
C8 "GRM188R72A104KA35D" FP-GRM188R72A104KA35D_0603-MFG 3805,768.07 r270 top
C9 "CGA6P1X7R2A106K250AC" FP-CGA6P1X7R2A106K250AC_1210-MFG 1162.24,2125.59 r0 top value=10µF
C10 "GRM188R72A104KA35D" FP-GRM188R72A104KA35D_0603-MFG 2464,1925 r270 top
C11 "GCJ188R72A104KA01D" 0603 305,760 r90 top value=0.1uF
C12 "CGA3E3X7S2A104K080AB" 0603S 1250,2374.28 r90 top value=0.1uF
C13 "GRM188R72A104KA35D" FP-GRM188R72A104KA35D_0603-MFG 2527,1925 r270 top
C14 "CGA6P1X7R2A106K250AC" FP-CGA6P1X7R2A106K250AC_1210-MFG 1157.24,1991.73 r0 top value=10µF
C15 "GRM155R62A104KE14D" 0402S 3140,2747.63 r180 top value=0.1uF
C16 "GRM155R62A104KE14D" 0402S 2355,3085 r0 top value=0.1uF
C17 "PCR1K270MCL1GS" FP-PCR1K270MCL1GS_SMT_CAP_8MM3_8MM3-MFG 1132.24,1625.59 r0 top value=27µF
C18 "PCR1K270MCL1GS" FP-PCR1K270MCL1GS_SMT_CAP_8MM3_8MM3-MFG 1132.24,1265.59 r0 top value=27µF
C19 "PCR1K270MCL1GS" FP-PCR1K270MCL1GS_SMT_CAP_8MM3_8MM3-MFG 1132.24,905.59 r0 top value=27µF
C20 "CGA6P1X7R2A106K250AC" FP-CGA6P1X7R2A106K250AC_1210-MFG 1157.24,1866.73 r0 top value=10µF
C21 "CGA6P1X7R2A106K250AC" FP-CGA6P1X7R2A106K250AC_1210-MFG 2620,1900 r270 top value=10µF
C22 "CGA6P1X7R2A106K250AC" FP-CGA6P1X7R2A106K250AC_1210-MFG 2740,1900 r270 top value=10µF
C23 "A768KE276M1JLAE054" FP-A768KE276M1JLAE054_SMT_CAP_8MM3_8MM3-0 2972.24,1635.59 r180 top value=27µF
C24 "GRM155R71H104ME14D" 0402S 2335,3025 r270 top value=0.1uF
C25 "GRM1555C1H271JA01D" 0402S 2335,2955 r270 top value=270pF
C26 "GRT188R61A226ME13D" 0603S 2750,2680 r90 top value=22µF
C27 "GRT188R61A226ME13D" 0603S 2375,2780 r270 top value=22µF
C28 "CGA3E3X7S2A104K080AB" 0603S 2695,2680 r90 top value=0.1uF
C29 "GRM155R62A104KE14D" 0402S 2800,2625 r90 top value=0.1uF
C30 "08051A681JAT2A" 0805_HV1 1651.18,1928.47 r90 top value=680pF
C31 "GCM155R71H104KE02D" 0402S 2380,2895 r270 top value=0.1uF
C32 "C0805C102J1GACTU" 0805_HV1 2060,1837.59 r90 top value=1000pF
C33 "GCM155R71H104KE02D" 0402S 2470,2705 r180 top value=0.1uF
C34 "06035A221FAT2A" 0603S 2550,3200 r180 top value=220pF
C35 "06035A560FAT2A" 0603S 2769.68,3195 r180 top value=56pF
C36 "C0603C123K5RACTU" 0603S 2550,3260 r180 top value=0.012uF
C37 "CC0603KRX7R9BB203" 0603S 2835,2705 r0 top value=0.02uF
C38 "06031C472JAT2A" 0603S 2470,3115 r90 top value=4700pF
C39 "06035C473JAT2A" 0603S 2440,3190 r0 top value=0.047uF
C40 "CGA6P1X7R2A106K250AC" FP-CGA6P1X7R2A106K250AC_1210-MFG 1162.24,2252.95 r0 top value=10µF
C41 "C3225X7R2A106K250AC" FP-C3225X7R2A106K250AC_1210-MFG 2462.5,655.91 r180 top value=10µF
C42 "C0603C472K5RACTU" 0603S 2150.85,1608.03 r0 top value=4700pF
C43 "C0603C681J5GACTU" 0603S 2592.17,2533.03 r0 top value=680pF
C44 "C0603C681J5GACTU" 0603S 2631.5,2260 r0 top value=680pF
D1 "BAS70-04-E3-18" FP-BAS70-04-E3-18_SOT23-3-MFG 1955,888.46 r180 top
D2 "SMBJ48A-13-F" SMB 1855.08,475.59 r180 bottom value=48V
D3 "SMBJ48A-13-F" SMB 2432.24,675.59 r0 bottom value=48V
FID1 "Fiducial" Fiducial10-20 527.43,3342.43 r0 top
FID2 "Fiducial" Fiducial10-20 860.46,140 r0 top
FID3 "Fiducial" Fiducial10-20 3183,140 r0 top
FID4 "Fiducial" Fiducial10-20 949.22,3073.82 r180 bottom
FID5 "Fiducial" Fiducial10-20 3010,295 r180 bottom
FID6 "Fiducial" Fiducial10-20 3166.69,2934 r180 bottom
H1 "PMSSS 440 0025 PH" B_F_PMSSS4400025PH 200,200 r0 top
H2 "PMSSS 440 0025 PH" B_F_PMSSS4400025PH 200,3400 r0 top
H3 "PMSSS 440 0025 PH" B_F_PMSSS4400025PH 3900,200 r0 top
H4 "PMSSS 440 0025 PH" B_F_PMSSS4400025PH 3900,3400 r0 top
J1 "108-0740-001" Johnson_108-0740-001 3505,440 r0 top
J2 "108-0740-001" Johnson_108-0740-001 600,440 r0 top
J3 "61300611121" WURTH_61300611121 205,760 r90 top
J4 "61300611121" WURTH_61300611121 3905,768.07 r90 top
J5 "108-0740-001" Johnson_108-0740-001 3505,1095 r0 top
J6 "108-0740-001" Johnson_108-0740-001 600,1085 r0 top
J7 "SSW-105-02-G-D-RA" FP-SSW-105-02-G-D-RA_HDR10-MFG 1142.09,163.07 r0 bottom
J8 "N2510-6002-RB" CONN_2510-6002 1350,3350 r0 top
J9 "XT30PW-F" FP-XT30PW-F_CONN_SOCKET_DC2-MFG 1843.66,-40.46 r0 bottom
J10 "XT30PW-M" FP-XT30PW-M_CONN_PLUG2-MFG 2443.66,172.8 r0 bottom
J11 "61300211121" WURTH_61300211121 3850,3000 r0 top
JP1 "61300311121" WURTH_61300311121 3800,1800 r0 top
JP2 "61300511121" Wurth_61300511121 3300,3248.86 r0 top
JP3 "61300311121" WURTH_61300311121 3800,1950 r180 top
JP4 "61300311121" WURTH_61300311121 3800,2100 r180 top
JP5 "61300311121" WURTH_61300311121 3800,3150 r180 top
JP6 "61300211121" WURTH_61300211121 3850,2250 r0 top
JP7 "61300311121" WURTH_61300311121 3400,3400 r0 top
JP8 "61300211121" WURTH_61300211121 3850,2700 r0 top
JP9 "61300311121" WURTH_61300311121 3800,2845 r180 top
JP10 "61300211121" WURTH_61300211121 3850,2400 r0 top
JP11 "61300211121" WURTH_61300211121 3850,2550 r0 top
JP12 "61300211121" WURTH_61300211121 1950,3400 r0 top
JP13 "61300211121" WURTH_61300211121 3850,2100 r180 top
L1 "74439370047" WE-XHMI_1510 2014.96,2273.61 r0 top value=4.7uH
Logo3 "FCC disclaimer" FCC_disclaimer 664.38,2565.42 r0 top
LOGO4 "WEEE logo" WEEE_Minimum 156.74,2393 r0 top (schematic designator Logo4)
Logo5 "CAUTION HOT SURFACE" IEC_HotSurface_Small 1931.89,2760 r0 top
Logo6 "CAUTION.  READ USER GUIDE BEFORE USE" IEC_Caution_Small 147.81,2813.29 r0 top
LOGO7 "DANGER HIGH VOLTAGE" IEC_HighVoltage_Medium 531.97,2209.06 r0 top
MP1 "1902D_Ndrill" FP-1902D_Ndrill_HEX_STANDOFF-MFG 3900,200 r180 bottom
MP2 "1902D_Ndrill" FP-1902D_Ndrill_HEX_STANDOFF-MFG 200,200 r180 bottom
MP3 "1902D_Ndrill" FP-1902D_Ndrill_HEX_STANDOFF-MFG 3900,3400 r180 bottom
MP4 "1902D_Ndrill" FP-1902D_Ndrill_HEX_STANDOFF-MFG 200,3400 r180 bottom
NT3 "Net-Tie" Net-Tie_10mil 2440.26,2815.5 r0 top net-tie
Q1 "IAUCN08S7L033ATMA1" FP-IAUCN08S7L033ATMA1_TDSON8-MFG 1499.01,1885.5 r180 top
Q1A "IAUCN08S7L033ATMA1" FP-IAUCN08S7L033ATMA1_TDSON8-MFG 1402.56,2220.07 r90 top
Q2 "IAUCN08S7L033ATMA1" FP-IAUCN08S7L033ATMA1_TDSON8-MFG 1502.73,2491.37 r270 top
Q3 "ISC0703NLSATMA1" FP-ISC0702NLSATMA1_SuperSO8-5x6-MFG 2450,2400 r90 top
Q3A "ISC0703NLSATMA1" FP-ISC0702NLSATMA1_SuperSO8-5x6-MFG 2450,2125 r90 top
Q4 "ISC0703NLSATMA1" FP-ISC0702NLSATMA1_SuperSO8-5x6-MFG 2277.91,1810.87 r270 top
Q5 "CSD18540Q5B" DNK0008A 2150,857.4 r270 top value=60V
R1 "RC0603FR-075K1L" 0603S 2015.1,1000 r90 top value=5.10k
R2 "RMCF0603ZT0R00" 0603S 3450,3143 r0 top value=0
R3 "KRL2012E-C-R010-F-T05" FP-KRL2012E-C-R010-F-T05_0508-MFG 2415,1095 r270 top value=10m
R4 "KRL2012E-M-R005-F-T5" FP-KRL2012E-M-R005-F-T5_0805_WIDE-MFG 1610.88,2133.7 r180 top value=5m
R5 "RMCF0603ZT0R00" 0603S 3136,2609.65 r0 top value=0
R6 "KRL2012E-M-R005-F-T5" FP-KRL2012E-M-R005-F-T5_0805_WIDE-MFG 1610.3,2266.3 r180 top value=5m
R7 "RMCF0603ZT0R00" 0603S 3030,2610 r180 top value=0
R8 "RC0603FR-0710RL" 0603S 3150,3150 r180 top value=10.0
R9 "RMCF0603ZT0R00" 0603S 2345,3160 r90 top value=0
R10 "RMCF0603ZT0R00" 0603S 2525,3115 r270 top value=0
R11 "RMCF0603ZT0R00" 0603S 3136,2665 r0 top value=0
R12 "RC0603FR-0782KL" 0603S 2635,3115 r90 top value=82.0k
R13 "CRCW06033R00JNEA" 0603S 1474.31,2079.08 r180 top value=3.0
R14 "CRCW06033R00JNEA" 0603S 1480.99,2355.87 r0 top value=3.0
R15 "RMCF0603ZT0R00" 0603S 2265,3020 r180 top value=0
R16 "RMCF0603ZT0R00" 0603S 2265,3075 r180 top value=0
R17 "CRCW060310R0FKEAHP" 0603S 2265,2910 r180 top value=10.0
R18 "CRCW060310R0FKEAHP" 0603S 2265,2965 r180 top value=10.0
R19 "RC0603FR-074K3L" 0603S 2580,3115 r270 top value=4.30k
R20 "RMCF0603ZT0R00" 0603S 2197.2,1669.42 r180 top value=0
R21 "RC0603FR-0775KL" 0603S 2930,2610 r0 top value=75.0k
R22 "RC0603FR-0712K7L" 0603S 2850,2630 r270 top value=12.7k
R23 "CRCW12063R00JNEA" 1206L 1658.13,1728.2 r270 top value=3.0
R24 "RMCF0603ZT0R00" 0603S 2835,2760 r180 top value=0
R25 "RT0603BRD0710KL" 0603S 2750,3115 r90 top value=10.0k
R26 "CRCW12063R00JNEA" 1206L 2060,1662.87 r270 top value=3.0
R27 "RMCF0603ZT0R00" 0603S 2835,2815 r180 top value=0
R28 "CRCW06033R00JNEA" 0603S 1340.28,2358.56 r0 top value=3.0
R29 "CRCW06037K15FKEA" 0603S 2635,3230 r270 top value=7.15k
R30 "CRCW060340K2FKEA" 0603S 2805,3115 r270 top value=40.2k
R31 "RC0603FR-0797K6L" 0603S 2695,3115 r270 top value=97.6k
R32 "CRCW06033R90JNEA" 0603S 2489.82,2540.92 r0 top value=3.9
R33 "CRCW06033R90JNEA" 0603S 2529.23,2261.97 r0 top value=3.9
R34 "CRCW060320K0FKEA" 0603S 2415,3115 r270 top value=20.0k
R35 "RC0603FR-07390KL" 0603S 2640,2680 r270 top value=390k
R36 "RMCF0603ZT0R00" 0603S 2865,3115 r270 top value=0
R37 "CRCW060320K5FKEA" 0603S 2835,2980 r180 top value=20.5k
R38 "RMCF0603ZT0R00" 0603S 2835,3035 r0 top value=0
R39 "RC0603FR-072KL" 0603S 1625,3255 r270 bottom value=2.00k
R40 "RC0603FR-072KL" 0603S 1685,3255 r270 bottom value=2.00k
R41 "CRCW06033K83FKEA" 0603S 2835,2870 r180 top value=3.83k
R42 "RC0603FR-078K25L" 0603S 2835,2925 r180 top value=8.25k
R43 "TNPW060310K0BEEA" TNPW0603 1909.14,1700 r90 top value=10.0k
R44 "RMCF0603ZT0R00" 0603S 3030,2665 r180 top value=0
RT1 "TMP6131DECR" DEC0002A-MFG 1966.58,1732.48 r270 top value=10k
SH-JP1 "M7582-05" Harwin_M7582-05 3748.45,1800 r180 top
SH-JP2 "M7582-05" Harwin_M7582-05 3450,3248.86 r180 top
SH-JP3 "M7582-05" Harwin_M7582-05 3847.9,1950 r180 top
SH-JP4 "M7582-05" Harwin_M7582-05 3847.9,2100.82 r180 top
SH-JP5 "M7582-05" Harwin_M7582-05 3850,3150 r180 top
SH-JP6 "M7582-05" Harwin_M7582-05 3846.83,2250 r180 top
SH-JP7 "M7582-05" Harwin_M7582-05 3450,3400 r180 top
SH-JP8 "M7582-05" Harwin_M7582-05 3847.9,2700 r180 top
SH-JP9 "M7582-05" Harwin_M7582-05 3850,2845 r180 top
SH-JP10 "M7582-05" Harwin_M7582-05 3848.9,2400 r180 top
SH-JP11 "M7582-05" Harwin_M7582-05 3848.9,2549.95 r180 top
SH-JP12 "M7582-05" Harwin_M7582-05 1947.89,3400 r180 top
TP1 "5013" Keystone5013 2650,1175 r90 top
TP2 "5013" Keystone5013 2650,1015 r90 top
TP3 "5010" Keystone5010 200,1410 r0 top
TP4 "5001" Keystone5001 2950,3400 r180 top
TP5 "RSP-122811-01" FP-RSP-122811-01_CONN_UFL-MFG 1550.32,2718.42 r0 top
TP6 "RSP-122811-01" FP-RSP-122811-01_CONN_UFL-MFG 2143.62,2737 r0 top
TP7 "5001" Keystone5001 2300,3400 r0 top
TP8 "5011" Keystone5011 200,1650 r270 top
TP9 "5004" Keystone5004 3650,3400 r90 top
TP10 "5004" Keystone5004 2150,3400 r0 top
TP11 "5004" Keystone5004 3900,1650 r0 top
TP12 "5004" Keystone5004 3100,3400 r180 top
TP13 "5004" Keystone5004 3900,1500 r0 top
U1 "LM851772QRHARQ1" RHA0040P-MFG 2540,2865 r180 top
ZZ2 "These assemblies are ESD sensitive, ESD precautions shall be observed." AssemblyNote 200,4000 r0 top
ZZ3 "These assemblies must be clean and free from flux and all contaminants. Use of no clean flux is not acceptable." AssemblyNote 200,3900 r0 top
ZZ4 "These assemblies must comply with workmanship standards IPC-A-610 Class 2, unless otherwise specified." AssemblyNote 200,3800 r0 top

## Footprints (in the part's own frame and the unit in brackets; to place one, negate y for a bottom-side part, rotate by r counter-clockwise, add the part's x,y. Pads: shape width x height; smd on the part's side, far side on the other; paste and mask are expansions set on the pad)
0402S [mil] "Based on C0402S footprint from PADS legacy"
  rect 15x24 smd: 1(-20,0) 2(20,0)
  body extent -22,-12 22,12, height 24
0603 [mm] "0603 from SM-752 data"
  rect 1x0.95 smd: 1(-0.8,0) 2(0.8,0)
  silkscreen extent -1.52,-0.69 1.52,0.69, body extent -0.87,-0.47 0.87,0.47, height 1
0603S [mil]
  rect 20x35 smd: 1(-30,0) 2(30,0)
  body extent -34,-19 34,19, height 39
0805_HV1 [mm] "Custom footprint based on analyzing multiple manufacturer recommendations"
  rrect10% 1x1.25 smd: 1(-1,0) 2(1,0)
  silkscreen extent -0.2,-0.75 0.2,0.75, body extent -1.1,-0.72 1.1,0.73, height 1.45
1206L [mm] "1206 from SM-752 data"
  rect 1.1x1.75 smd: 1(-1.35,0) 2(1.35,0)
  silkscreen extent -0.4,-0.77 0.4,0.77, body extent -1.7,-0.9 1.7,0.9, height 1.35
AssemblyNote [mil] "Assembly Note"
B_F_PMSSS4400025PH [mil] "MACHINE SCREW PAN PHILLIPS 4-40"
  round 230 hole 125: 1(0,0)
  body extent -109,-109 110,110, height 79
CONN_2510-6002 [mm] "3M 2500 series TS-0770-L December 15, 2011"
  rect 1.65x1.65 hole 1.016 mask+0: 1(-5.08,-1.27)
  round 1.65 hole 1.016 mask+0: 2(-5.08,1.27) 3(-2.54,-1.27) 4(-2.54,1.27) 5(0,-1.27) 6(0,1.27) 7(2.54,-1.27) 8(2.54,1.27) 9(5.08,-1.27) 10(5.08,1.27)
  silkscreen extent -10.01,-4.17 10.01,4.47, body extent -10.01,-4.11 10.01,4.52, height 9.92
DEC0002A-MFG [mm]
  rrect40% 0.25x0.5 smd paste-1000 mask+0: 1(-0.325,0) 2(0.325,0)
  silkscreen extent -0.98,0.15 -0.83,0.3, body extent -0.63,-0.43 0.63,0.43, height 0.25
DNK0008A [mm] "SON, 8-Leads, Body 5x6mm"
  rrect39% 0.86x0.51 smd paste-0.05 mask-0.05: 1(-2.82,1.905) 2(-2.82,0.635) 3(-2.82,-0.635) 4(-2.82,-1.905) 5(2.82,-1.905) 6(2.82,-0.635) 7(2.82,0.635) 8(2.82,1.905)
  rrect40% 0.25x0.555 on Top Paste: 9(-0.83,2.372) 9(-0.83,-2.372)
  rrect40% 0.25x0.555 on Top Solder: 9(-0.83,2.372) 9(-0.83,-2.372)
  rrect11% 0.95x1.13 on Top Paste: 9(-0.535,1.33) 9(-0.535,0) 9(-0.535,-1.33) 9(0.615,1.33) 9(0.615,0) 9(0.615,-1.33) 9(1.765,1.33) 9(1.765,0) 9(1.765,-1.33)
  rrect3% 3.58x4 on Top Solder: 9(0.75,0)
  rrect5% 4.34x5.4 smd paste-3 mask-3: 9(1.08,0)
  body extent -3.05,-2.55 3.05,2.55, height 1.06
FCC_disclaimer [mil]
Fiducial10-20 [mm]
  round 1 smd mask+0.5: 1(0,0)
  Top Layer keep-out circle w1.178: c0,0 r0.5
FP-1902D_Ndrill_HEX_STANDOFF-MFG [mil]
  body extent -144,-125 144,125, height 765
FP-A768KE276M1JLAE054_SMT_CAP_8MM3_8MM3-0 [mm]
  rrect5% 4.2x2.2 smd paste+0 mask+0: 1(-3.65,0) 2(3.65,0)
  silkscreen extent -4.25,-4.25 4.25,4.25, body extent -6,-4.5 6,4.5, height 0.25
FP-BAS70-04-E3-18_SOT23-3-MFG [mm]
  rrect14% 0.9x0.7 smd paste+0 mask+0: 1(-1,0.95) 2(-1,-0.95) 3(1,0)
  silkscreen extent -0.71,-1.55 0.71,1.55, body extent -1.24,-1.48 1.24,1.48, height 1.15
FP-C3225X7R2A106K250AC_1210-MFG [mm]
  rrect9% 1.1x2.2 smd paste+0 mask+0: 1(-1.65,0) 2(1.65,0)
  silkscreen extent -0.72,-1.43 0.72,1.43, body extent -2.3,-1.53 2.3,1.53, height 0.25
FP-CGA6P1X7R2A106K250AC_1210-MFG [mm] "Recommended Land Pattern"
  rrect9% 1.1x2.2 smd paste+0 mask+0: 1(-1.65,0) 2(1.65,0)
  silkscreen extent -0.72,-1.4 0.72,1.4, body extent -1.6,-1.25 1.6,1.25, height 2.81
FP-GRM188R72A104KA35D_0603-MFG [mm]
  rrect15% 0.65x0.7 smd paste+0 mask+0: 1(-0.675,0) 2(0.675,0)
  silkscreen extent -0.85,-0.72 0.85,0.72, body extent -1.1,-0.55 1.1,0.55, height 0.25
FP-IAUCN08S7L033ATMA1_TDSON8-MFG [mm] "Recommended Land Pattern"
  rrect7% 3.14x1.5 smd paste-1000 mask-1000: 1-2-3(-0.635,-3.02)
  rrect17% 0.6x1.5 smd paste-1000 mask+0: 4(1.905,-3.02)
  rrect2% 4.41x4.9 smd paste-1000 mask-1000: 5-6-7-8(0,1.32)
  silkscreen extent -2.63,-4.47 2.63,2.79, body extent -2.71,-3.22 2.71,3.22, height 1.1
FP-ISC0702NLSATMA1_SuperSO8-5x6-MFG [mm]
  rrect20% 0.5x0.925 smd paste-1000 mask+0: 1(-1.905,-2.865) 2(-0.635,-2.865) 3(0.635,-2.865) 4(1.905,-2.865)
  rrect2% 4.41x4.455 smd paste-1000 mask-1000: 5-6-7-8(0,1.098)
  silkscreen extent -2.68,-4 2.68,3.05, body extent -2.88,-3.43 2.88,3.43, height 0.25
FP-KRL2012E-C-R010-F-T05_0508-MFG [mm]
  rrect14% 0.7x2.2 smd paste+0 mask+0: 1(-0.65,0) 2(0.65,0)
  silkscreen extent -0.72,-1.5 0.72,1.5, body extent -1.1,-1.2 1.1,1.2, height 0.25
FP-KRL2012E-M-R005-F-T5_0805_WIDE-MFG [mm]
  rrect14% 0.7x2.2 smd paste+0 mask+0: 1(-0.65,0) 2(0.65,0)
  silkscreen extent -0.72,-1.5 0.72,1.5, body extent -1.1,-1.2 1.1,1.2, height 0.25
FP-PCR1K270MCL1GS_SMT_CAP_8MM3_8MM3-MFG [mm] "Recommended Land Pattern"
  rrect5% 3.5x2 smd paste+0 mask+0: 1(-3.25,0) 2(3.25,0)
  silkscreen extent -4.87,-4.25 4.25,4.25, body extent -4.5,-4.15 4.5,4.15, height 10.1
FP-RSP-122811-01_CONN_UFL-MFG [mm] "Recommended Land Pattern"
  rrect10% 1x1.05 smd paste+0 mask+0: 1(0,-1.525)
  rrect10% 1.05x2.2 smd paste+0 mask+0: 2(-1.475,0) 3(1.475,0)
  silkscreen extent -1.35,-2.75 1.35,1.6, body extent -2.1,-2.15 2.1,1.7, height 0.25
FP-SSW-105-02-G-D-RA_HDR10-MFG [mm]
  rrect6% 1.59x1.59 hole 1.04 paste-2539.97 mask+0: 1(-5.08,-5.779)
  round 1.59 hole 1.04 paste-2539.97 mask+0: 2(-5.08,-8.319) 3(-2.54,-5.779) 4(-2.54,-8.319) 5(0,-5.779) 6(0,-8.319) 7(2.54,-5.779) 8(2.54,-8.319) 9(5.08,-5.779) 10(5.08,-8.319)
  silkscreen extent -6.73,-5.9 6.73,4.39, body extent -6.61,-8.52 6.61,4.25, height 5.08
FP-XT30PW-F_CONN_SOCKET_DC2-MFG [mm]
  rrect4% 2.6x2.6 hole 1.7 paste-2539.97 mask+0: 1(-2.5,-8.825)
  round 2.6 hole 1.7 paste-2539.97 mask+0: 2(2.5,-8.825)
  round 1.55 hole 1 paste-2539.97 mask+0: 3(-5.5,-3.825) 4(5.5,-3.825)
  silkscreen extent -6.65,-8.95 6.65,5.07, body extent -6.65,-9.83 6.65,5.07, height 5
FP-XT30PW-M_CONN_PLUG2-MFG [mm]
  rrect4% 2.6x2.6 hole 1.7 paste-2539.97 mask+0: 1(2.5,-8.6)
  round 2.6 hole 1.7 paste-2539.97 mask+0: 2(-2.5,-8.6)
  round 1.55 hole 1 paste-2539.97 mask+0: 3(-5.5,1.4) 4(5.5,1.4)
  silkscreen extent -6.65,-8.72 6.65,4.5, body extent -6.65,-9.45 6.65,4.5, height 5.1
Harwin_M7582-05 [mil] "Single Operation 2.54mm Pitch Open Top Jumper Socket"
  body extent -98,-47 98,47, height 236
IEC_Caution_Small [mil]
  silkscreen extent -107,-93 107,92
IEC_HighVoltage_Medium [mil]
  silkscreen extent -217,-176 217,200
IEC_HotSurface_Small [mil]
  silkscreen extent -107,-93 107,92
Johnson_108-0740-001 [mm] "Banana Jack Uninsulated Standard Type"
  round 12 hole 6.858: 1(0,0)
  body extent -4.77,-5.43 4.75,5.57, height 2.39
Keystone5001 [mil] "For Keystone 500x miniature loop terminals"
  round 80 hole 40: 1(0,0)
  silkscreen extent -52,-52 52,52, body extent -49,-49 49,49, height 182
Keystone5004 [mil] "For Keystone 500x miniature loop terminals"
  round 80 hole 40: 1(0,0)
  silkscreen extent -52,-52 52,52, body extent -49,-49 49,49, height 182
Keystone5010 [mil] "Keystone Multipurpose loops"
  round 87 hole 63: 1(0,0)
  silkscreen extent -70,-70 70,70, body extent -63,-63 63,62, height 319
Keystone5011 [mil] "Keystone Multipurpose loops"
  round 87 hole 63: 1(0,0)
  silkscreen extent -70,-70 70,70, body extent -63,-63 63,62, height 319
Keystone5013 [mil] "Keystone Multipurpose loops"
  round 87 hole 63: 1(0,0)
  silkscreen extent -70,-70 70,70, body extent -63,-63 63,62, height 319
Net-Tie_10mil [mil] "10mil net tie, no solder mask opening, no solder paste"
  rect 10x10 smd paste-5 mask-5: 1(-10,0) 2(10,0)
  Top Layer region: -6,5 6,5 6,-5 -6,-5
RHA0040P-MFG [mm] "Recommended Land Pattern"
  rrect40% 0.6x0.25 smd paste+0 mask+0: 1(-2.9,2.25) 2(-2.9,1.75) 3(-2.9,1.25) 4(-2.9,0.75) 5(-2.9,0.25) 6(-2.9,-0.25) 7(-2.9,-0.75) 8(-2.9,-1.25) 9(-2.9,-1.75) 10(-2.9,-2.25) 21(2.9,-2.25) 22(2.9,-1.75) 23(2.9,-1.25) 24(2.9,-0.75) 25(2.9,-0.25) 26(2.9,0.25) 27(2.9,0.75) 28(2.9,1.25) 29(2.9,1.75) 30(2.9,2.25)
  rrect40% 0.25x0.6 smd paste+0 mask+0: 11(-2.25,-2.9) 12(-1.75,-2.9) 13(-1.25,-2.9) 14(-0.75,-2.9) 15(-0.25,-2.9) 16(0.25,-2.9) 17(0.75,-2.9) 18(1.25,-2.9) 19(1.75,-2.9) 20(2.25,-2.9) 31(2.25,2.9) 32(1.75,2.9) 33(1.25,2.9) 34(0.75,2.9) 35(0.25,2.9) 36(-0.25,2.9) 37(-0.75,2.9) 38(-1.25,2.9) 39(-1.75,2.9) 40(-2.25,2.9)
  rrect3% 3.3x3.3 smd paste-1000 mask+0: 41(0,0)
  silkscreen extent -3.88,-3.05 3.05,3.05, body extent -3,-3 3,3, height 1
SMB [mil] "Molded Diode, 2-Leads, Body 5.4x3.6mm, IPC Medium Density, based on OnSemi component dimensions"
  rect 85x107.99 smd: 1(-87.01,0) 2(87.01,0)
  silkscreen extent -155,-82 125,82, body extent -106,-71 106,71, height 91
TNPW0603 [mm] "Vishay"
  rect 0.5x0.9 smd: 1(-0.75,0) 2(0.75,0)
  silkscreen extent -0.2,-0.6 0.2,0.6, body extent -0.85,-0.47 0.85,0.47, height 0.55
WE-XHMI_1510 [mm] "SMD, 2-Leads, Body 16.4x15.4mm"
  rrect3% 3.3x14.1 smd: 1(-5.3,0) 2(5.3,0)
  body extent -7.67,-8.17 7.73,8.23, height 10.03
WEEE_Minimum [mil] "WEEElie bin"
  silkscreen extent -95,-172 99,104
WURTH_61300211121 [mm] "Header, 2.54mm, 2x1, TH"
  rrect50% 1.65x1.65 hole 1.15: 1(-1.27,0)
  round 1.65 hole 1.15: 2(1.27,0)
  body extent -2.54,-1.27 2.54,1.27, height 8.54
WURTH_61300311121 [mm] "Header, 2.54mm, 3x1, TH"
  rrect50% 1.65x1.65 hole 1.15: 1(-2.54,0)
  round 1.65 hole 1.15: 2(0,0) 3(2.54,0)
  body extent -3.81,-1.27 3.81,1.27, height 8.54
Wurth_61300511121 [mm] "Header, 2.54mm, 5x1, TH"
  rrect50% 1.65x1.65 hole 1.1: 1(-5.08,0)
  round 1.65 hole 1.1: 2(-2.54,0) 3(0,0) 4(2.54,0) 5(5.08,0)
  body extent -6.35,-1.27 6.35,1.27, height 8.54
WURTH_61300611121 [mm] "Header, 2.54mm, 6x1, TH"
  rrect50% 1.65x1.65 hole 1.15: 1(-6.35,0)
  round 1.65 hole 1.15: 2(-3.81,0) 3(-1.27,0) 4(1.27,0) 5(3.81,0) 6(6.35,0)
  body extent -7.62,-1.27 7.62,1.27, height 8.54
